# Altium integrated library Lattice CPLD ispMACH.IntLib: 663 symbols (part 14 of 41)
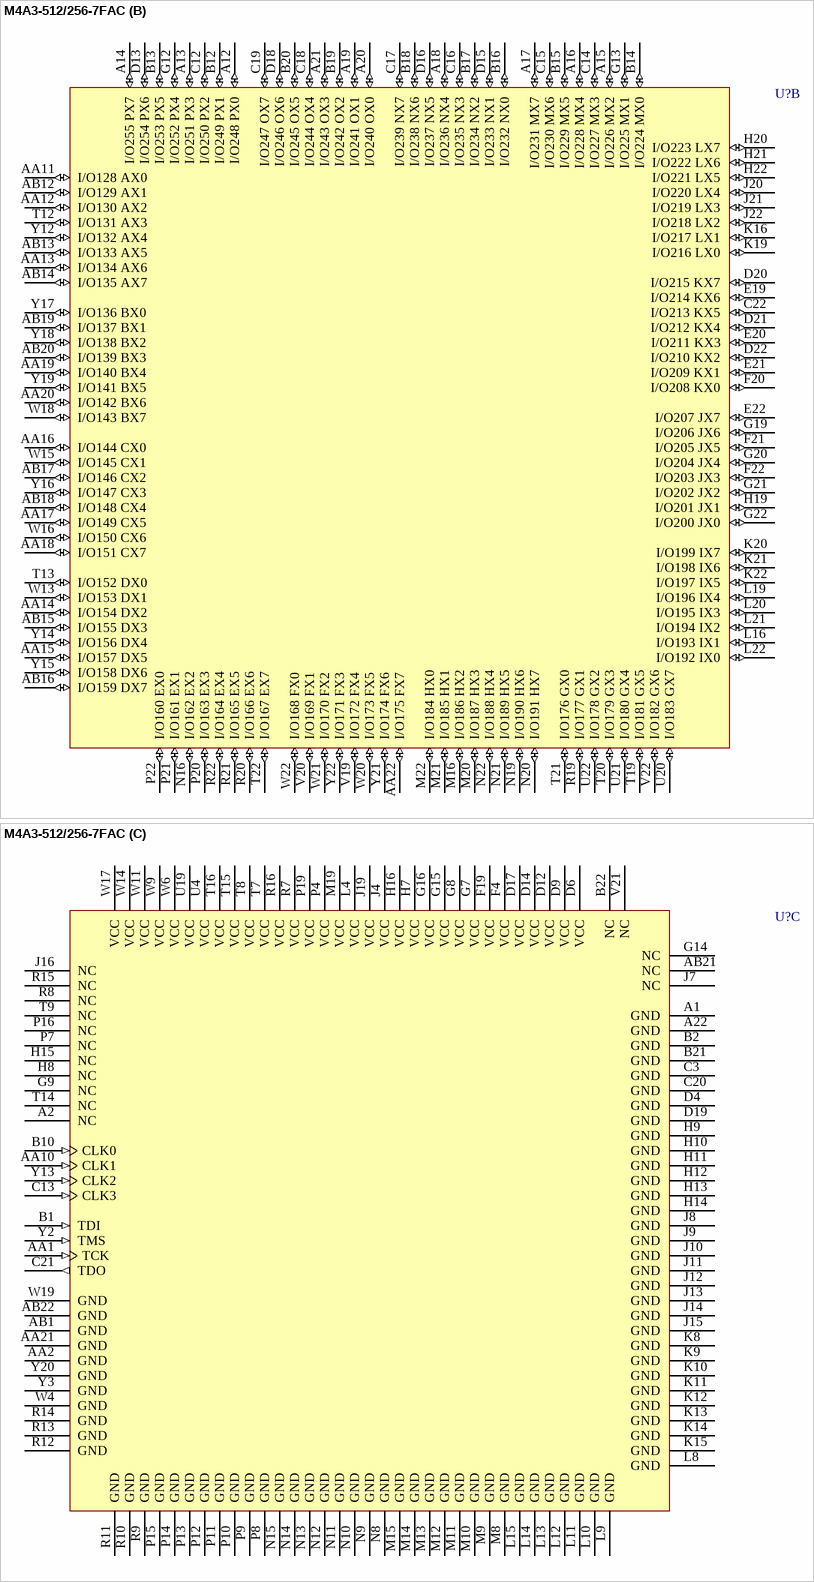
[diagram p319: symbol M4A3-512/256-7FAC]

## M4A3-512/256-7FAC
designator U?
High-Performance EE CMOS In-System Programmable Logic
footprint fpBGA388 (BGA, 388-Leads, Body 23x23mm, Pitch 1mm)
3D model M4A3-fpBGA388 (388-Ball Fine Pitch Ball Grid Array (fpBGA388))
part A pins: A3 I/O10 B2 (io), A4 I/O8 B0 (io), A5 I/O22 C6 (io), A6 I/O17 C1 (io), A7 I/O30 D6 (io), A8 I/O27 D3 (io), A9 I/O6 A6 (io), A10 I/O5 A5 (io), A11 I/O0 A0 (io), AA3 I/O116 O4 (io), AA4 I/O113 O1 (io), AA5 I/O109 N5 (io), AA6 I/O108 N4 (io), AA7 I/O103 M7 (io), AA8 I/O100 M4 (io), AA9 I/O127 P7 (io), AB2 I/O117 O5 (io), AB3 I/O114 O2 (io), AB4 I/O112 O0 (io), AB5 I/O107 N3 (io), AB6 I/O105 N1 (io), AB7 I/O102 M6 (io), AB8 I/O97 M1 (io), AB9 I/O126 P6 (io), AB10 I/O124 P4 (io), AB11 I/O120 P0 (io), B3 I/O13 B5 (io), B4 I/O12 B4 (io), B5 I/O9 B1 (io), B6 I/O20 C4 (io), B7 I/O31 D7 (io), B8 I/O29 D5 (io), B9 I/O26 D2 (io), B11 I/O2 A2 (io), C1 I/O44 F4 (io), C2 I/O47 F7 (io), C4 I/O15 B7 (io), C5 I/O11 B3 (io), C6 I/O23 C7 (io), C7 I/O18 C2 (io), C8 I/O16 C0 (io), C9 I/O25 D1 (io), C10 I/O7 A7 (io), C11 I/O11 A1 (io), D1 I/O41 F1 (io), D2 I/O43 F3 (io), D3 I/O46 F6 (io), D5 I/O14 B6 (io), D7 I/O21 C5 (io), D8 I/O19 C3 (io), D10 I/O24 D0 (io), D11 I/O3 A3 (io), E1 I/O54 G6 (io), E2 I/O40 F0 (io), E3 I/O42 F2 (io), E4 I/O45 F5 (io), F1 I/O50 G2 (io), F2 I/O52 G4 (io), F3 I/O55 G7 (io), G1 I/O39 E7 (io), G2 I/O49 G1 (io), G3 I/O51 G3 (io), G4 I/O53 G5 (io), G10 I/O28 D4 (io), G11 I/O4 A4 (io), H1 I/O36 E4 (io), H2 I/O37 E5 (io), H3 I/O38 E6 (io), H4 I/O48 G0 (io), J1 I/O32 E0 (io), J2 I/O34 E2 (io), J3 I/O35 E3 (io), K1 I/O60 H4 (io), K2 I/O61 H5 (io), K3 I/O62 H6 (io), K4 I/O63 H7 (io), K7 I/O33 E1 (io), L1 I/O56 H0 (io), L2 I/O57 H1 (io), L3 I/O59 H3 (io), L7 I/O58 H2 (io), M1 I/O64 I0 (io), M2 I/O66 I2 (io), M3 I/O65 I1 (io), M4 I/O67 I3 (io), M7 I/O69 I5 (io), N1 I/O68 I4 (io), N2 I/O70 I6 (io), N3 I/O71 I7 (io), N4 I/O88 L0 (io), N7 I/O89 L1 (io), P1 I/O90 L2 (io), P2 I/O91 L3 (io), P3 I/O92 L4 (io), R1 I/O93 L5 (io), R2 I/O94 L6 (io), R3 I/O95 L7 (io), R4 I/O74 J2 (io), T1 I/O72 J0 (io), T2 I/O73 J1 (io), T3 I/O76 J4 (io), T4 I/O78 J6 (io), T10 I/O98 M2 (io), T11 I/O122 P2 (io), U1 I/O75 J3 (io), U2 I/O77 J5 (io), U3 I/O80 K0 (io), V1 I/O79 J7 (io), V2 I/O81 K1 (io), V3 I/O83 K3 (io), V4 I/O86 K6 (io), W1 I/O82 K2 (io), W2 I/O84 K4 (io), W3 I/O87 K7 (io), W5 I/O119 O7 (io), W7 I/O111 N7 (io), W8 I/O104 N0 (io), W10 I/O96 M0 (io), W12 I/O123 P3 (io), Y1 I/O85 K5 (io), Y4 I/O118 O6 (io), Y5 I/O115 O3 (io), Y6 I/O110 N6 (io), Y7 I/O106 N2 (io), Y8 I/O101 M5 (io), Y9 I/O99 M3 (io), Y10 I/O125 P5 (io), Y11 I/O121 P1 (io)
part B pins: A12 I/O248 PX0 (io), A13 I/O251 PX3 (io), A14 I/O255 PX7 (io), A15 I/O226 MX2 (io), A16 I/O228 MX4 (io), A17 I/O231 MX7 (io), A18 I/O236 NX4 (io), A19 I/O241 OX1 (io), A20 I/O240 OX0 (io), A21 I/O243 OX3 (io), AA11 I/O128 AX0 (io), AA12 I/O130 AX2 (io), AA13 I/O134 AX6 (io), AA14 I/O154 DX2 (io), AA15 I/O157 DX5 (io), AA16 I/O144 CX0 (io), AA17 I/O149 CX5 (io), AA18 I/O151 CX7 (io), AA19 I/O140 BX4 (io), AA20 I/O142 BX6 (io), AA22 I/O175 FX7 (io), AB12 I/O129 AX1 (io), AB13 I/O133 AX5 (io), AB14 I/O135 AX7 (io), AB15 I/O155 DX3 (io), AB16 I/O159 DX7 (io), AB17 I/O146 CX2 (io), AB18 I/O148 CX4 (io), AB19 I/O137 BX1 (io), AB20 I/O139 BX3 (io), B12 I/O249 PX1 (io), B13 I/O253 PX5 (io), B14 I/O224 MX0 (io), B15 I/O229 MX5 (io), B16 I/O232 NX0 (io), B17 I/O234 NX2 (io), B18 I/O238 NX6 (io), B19 I/O242 OX2 (io), B20 I/O245 OX5 (io), C12 I/O250 PX2 (io), C14 I/O227 MX3 (io), C15 I/O230 MX6 (io), C16 I/O235 NX3 (io), C17 I/O239 NX7 (io), C18 I/O244 OX4 (io), C19 I/O247 OX7 (io), C22 I/O213 KX5 (io), D13 I/O254 PX6 (io), D15 I/O233 NX1 (io), D16 I/O237 NX5 (io), D18 I/O246 OX6 (io), D20 I/O215 KX7 (io), D21 I/O212 KX4 (io), D22 I/O210 KX2 (io), E19 I/O214 KX6 (io), E20 I/O211 KX3 (io), E21 I/O209 KX1 (io), E22 I/O207 JX7 (io), F20 I/O208 KX0 (io), F21 I/O205 JX5 (io), F22 I/O203 JX3 (io), G12 I/O252 PX4 (io), G13 I/O225 MX1 (io), G19 I/O206 JX6 (io), G20 I/O204 JX4 (io), G21 I/O202 JX2 (io), G22 I/O200 JX0 (io), H19 I/O201 JX1 (io), H20 I/O223 LX7 (io), H21 I/O222 LX6 (io), H22 I/O221 LX5 (io), J20 I/O220 LX4 (io), J21 I/O219 LX3 (io), J22 I/O218 LX2 (io), K16 I/O217 LX1 (io), K19 I/O216 LX0 (io), K20 I/O199 IX7 (io), K21 I/O198 IX6 (io), K22 I/O197 IX5 (io), L16 I/O193 IX1 (io), L19 I/O196 IX4 (io), L20 I/O195 IX3 (io), L21 I/O194 IX2 (io), L22 I/O192 IX0 (io), M16 I/O186 HX2 (io), M20 I/O187 HX3 (io), M21 I/O185 HX1 (io), M22 I/O184 HX0 (io), N16 I/O162 EX2 (io), N19 I/O190 HX6 (io), N20 I/O191 HX7 (io), N21 I/O189 HX5 (io), N22 I/O188 HX4 (io), P20 I/O163 EX3 (io), P21 I/O161 EX1 (io), P22 I/O160 EX0 (io), R19 I/O177 GX1 (io), R20 I/O166 EX6 (io), R21 I/O165 EX5 (io), R22 I/O164 EX4 (io), T12 I/O131 AX3 (io), T13 I/O152 DX0 (io), T19 I/O181 GX5 (io), T20 I/O179 GX3 (io), T21 I/O176 GX0 (io), T22 I/O167 EX7 (io), U20 I/O183 GX7 (io), U21 I/O180 GX4 (io), U22 I/O178 GX2 (io), V19 I/O172 FX4 (io), V20 I/O169 FX1 (io), V22 I/O182 GX6 (io), W13 I/O153 DX1 (io), W15 I/O145 CX1 (io), W16 I/O150 CX6 (io), W18 I/O143 BX7 (io), W20 I/O173 FX5 (io), W21 I/O170 FX2 (io), W22 I/O168 FX0 (io), Y12 I/O132 AX4 (io), Y14 I/O156 DX4 (io), Y15 I/O158 DX6 (io), Y16 I/O147 CX3 (io), Y17 I/O136 BX0 (io), Y18 I/O138 BX2 (io), Y19 I/O141 BX5 (io), Y21 I/O174 FX6 (io), Y22 I/O171 FX3 (io)
part C pins: A1 GND (power), A2 NC, A22 GND (power), AA1 TCK (in), AA2 GND (power), AA10 CLK1 (in), AA21 GND (power), AB1 GND (power), AB21 NC, AB22 GND (power), B1 TDI (in), B2 GND (power), B10 CLK0 (in), B21 GND (power), B22 NC, C3 GND (power), C13 CLK3 (in), C20 GND (power), C21 TDO (out), D4 GND (power), D6 VCC (power), D9 VCC (power), D12 VCC (power), D14 VCC (power), D17 VCC (power), D19 GND (power), F4 VCC (power), F19 VCC (power), G7 VCC (power), G8 VCC (power), G9 NC, G14 NC, G15 VCC (power), G16 VCC (power), H7 VCC (power), H8 NC, H9 GND (power), H10 GND (power), H11 GND (power), H12 GND (power), H13 GND (power), H14 GND (power), H15 NC, H16 VCC (power), J4 VCC (power), J7 NC, J8 GND (power), J9 GND (power), J10 GND (power), J11 GND (power), J12 GND (power), J13 GND (power), J14 GND (power), J15 GND (power), J16 NC, J19 VCC (power), K8 GND (power), K9 GND (power), K10 GND (power), K11 GND (power), K12 GND (power), K13 GND (power), K14 GND (power), K15 GND (power), L4 VCC (power), L8 GND (power), L9 GND (power), L10 GND (power), L11 GND (power), L12 GND (power), L13 GND (power), L14 GND (power), L15 GND (power), M8 GND (power), M9 GND (power), M10 GND (power), M11 GND (power), M12 GND (power), M13 GND (power), M14 GND (power), M15 GND (power), M19 VCC (power), N8 GND (power), N9 GND (power), N10 GND (power), N11 GND (power), N12 GND (power), N13 GND (power), N14 GND (power), N15 GND (power), P4 VCC (power), P7 NC, P8 GND (power), P9 GND (power), P10 GND (power), P11 GND (power), P12 GND (power), P13 GND (power), P14 GND (power), P15 GND (power), P16 NC, P19 VCC (power), R7 VCC (power), R8 NC, R9 GND (power), R10 GND (power), R11 GND (power), R12 GND (power), R13 GND (power), R14 GND (power), R15 NC, R16 VCC (power), T7 VCC (power), T8 VCC (power), T9 NC, T14 NC, T15 VCC (power), T16 VCC (power), U4 VCC (power), U19 VCC (power), V21 NC, W4 GND (power), W6 VCC (power), W9 VCC (power), W11 VCC (power), W14 VCC (power), W17 VCC (power), W19 GND (power), Y2 TMS (in), Y3 GND (power), Y13 CLK2 (in), Y20 GND (power)

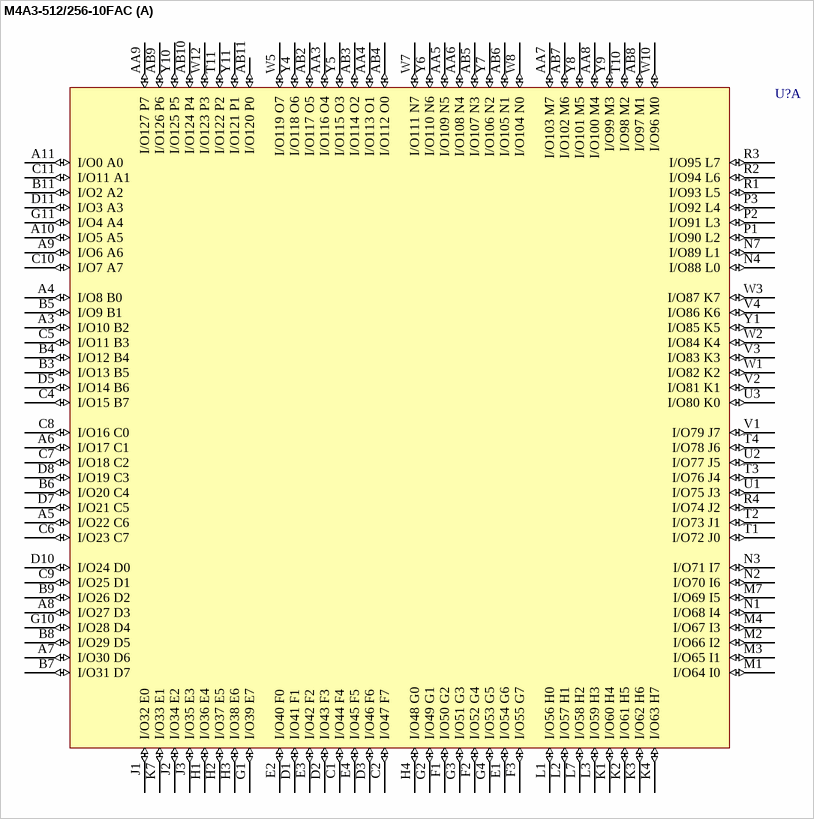
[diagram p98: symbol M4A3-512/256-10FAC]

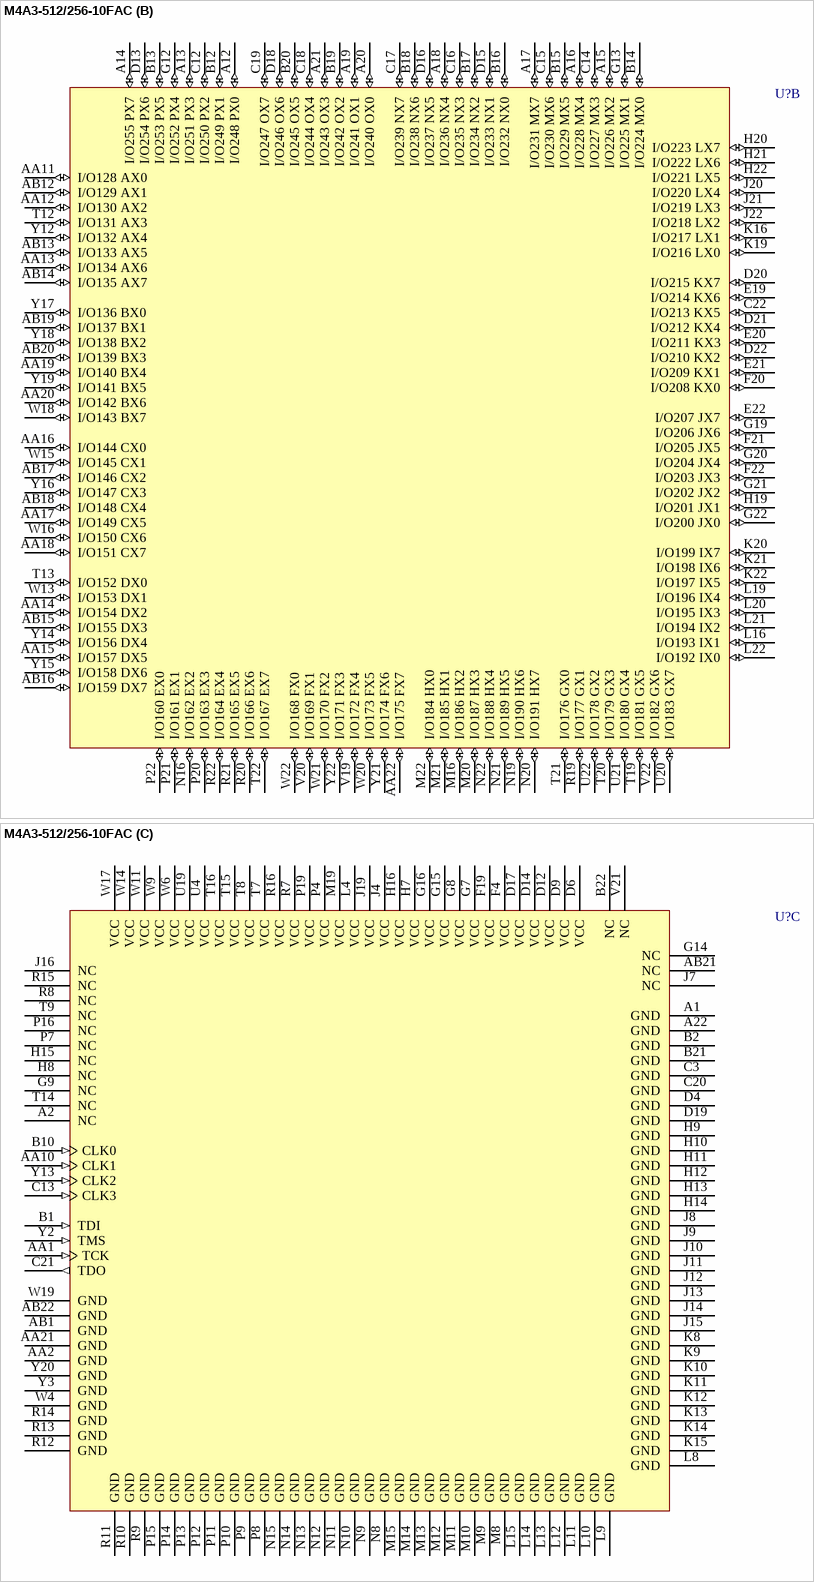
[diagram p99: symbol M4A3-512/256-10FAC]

## M4A3-512/256-10FAC
designator U?
High-Performance EE CMOS In-System Programmable Logic
footprint fpBGA388 (BGA, 388-Leads, Body 23x23mm, Pitch 1mm)
3D model M4A3-fpBGA388 (388-Ball Fine Pitch Ball Grid Array (fpBGA388))
part A pins: A3 I/O10 B2 (io), A4 I/O8 B0 (io), A5 I/O22 C6 (io), A6 I/O17 C1 (io), A7 I/O30 D6 (io), A8 I/O27 D3 (io), A9 I/O6 A6 (io), A10 I/O5 A5 (io), A11 I/O0 A0 (io), AA3 I/O116 O4 (io), AA4 I/O113 O1 (io), AA5 I/O109 N5 (io), AA6 I/O108 N4 (io), AA7 I/O103 M7 (io), AA8 I/O100 M4 (io), AA9 I/O127 P7 (io), AB2 I/O117 O5 (io), AB3 I/O114 O2 (io), AB4 I/O112 O0 (io), AB5 I/O107 N3 (io), AB6 I/O105 N1 (io), AB7 I/O102 M6 (io), AB8 I/O97 M1 (io), AB9 I/O126 P6 (io), AB10 I/O124 P4 (io), AB11 I/O120 P0 (io), B3 I/O13 B5 (io), B4 I/O12 B4 (io), B5 I/O9 B1 (io), B6 I/O20 C4 (io), B7 I/O31 D7 (io), B8 I/O29 D5 (io), B9 I/O26 D2 (io), B11 I/O2 A2 (io), C1 I/O44 F4 (io), C2 I/O47 F7 (io), C4 I/O15 B7 (io), C5 I/O11 B3 (io), C6 I/O23 C7 (io), C7 I/O18 C2 (io), C8 I/O16 C0 (io), C9 I/O25 D1 (io), C10 I/O7 A7 (io), C11 I/O11 A1 (io), D1 I/O41 F1 (io), D2 I/O43 F3 (io), D3 I/O46 F6 (io), D5 I/O14 B6 (io), D7 I/O21 C5 (io), D8 I/O19 C3 (io), D10 I/O24 D0 (io), D11 I/O3 A3 (io), E1 I/O54 G6 (io), E2 I/O40 F0 (io), E3 I/O42 F2 (io), E4 I/O45 F5 (io), F1 I/O50 G2 (io), F2 I/O52 G4 (io), F3 I/O55 G7 (io), G1 I/O39 E7 (io), G2 I/O49 G1 (io), G3 I/O51 G3 (io), G4 I/O53 G5 (io), G10 I/O28 D4 (io), G11 I/O4 A4 (io), H1 I/O36 E4 (io), H2 I/O37 E5 (io), H3 I/O38 E6 (io), H4 I/O48 G0 (io), J1 I/O32 E0 (io), J2 I/O34 E2 (io), J3 I/O35 E3 (io), K1 I/O60 H4 (io), K2 I/O61 H5 (io), K3 I/O62 H6 (io), K4 I/O63 H7 (io), K7 I/O33 E1 (io), L1 I/O56 H0 (io), L2 I/O57 H1 (io), L3 I/O59 H3 (io), L7 I/O58 H2 (io), M1 I/O64 I0 (io), M2 I/O66 I2 (io), M3 I/O65 I1 (io), M4 I/O67 I3 (io), M7 I/O69 I5 (io), N1 I/O68 I4 (io), N2 I/O70 I6 (io), N3 I/O71 I7 (io), N4 I/O88 L0 (io), N7 I/O89 L1 (io), P1 I/O90 L2 (io), P2 I/O91 L3 (io), P3 I/O92 L4 (io), R1 I/O93 L5 (io), R2 I/O94 L6 (io), R3 I/O95 L7 (io), R4 I/O74 J2 (io), T1 I/O72 J0 (io), T2 I/O73 J1 (io), T3 I/O76 J4 (io), T4 I/O78 J6 (io), T10 I/O98 M2 (io), T11 I/O122 P2 (io), U1 I/O75 J3 (io), U2 I/O77 J5 (io), U3 I/O80 K0 (io), V1 I/O79 J7 (io), V2 I/O81 K1 (io), V3 I/O83 K3 (io), V4 I/O86 K6 (io), W1 I/O82 K2 (io), W2 I/O84 K4 (io), W3 I/O87 K7 (io), W5 I/O119 O7 (io), W7 I/O111 N7 (io), W8 I/O104 N0 (io), W10 I/O96 M0 (io), W12 I/O123 P3 (io), Y1 I/O85 K5 (io), Y4 I/O118 O6 (io), Y5 I/O115 O3 (io), Y6 I/O110 N6 (io), Y7 I/O106 N2 (io), Y8 I/O101 M5 (io), Y9 I/O99 M3 (io), Y10 I/O125 P5 (io), Y11 I/O121 P1 (io)
part B pins: A12 I/O248 PX0 (io), A13 I/O251 PX3 (io), A14 I/O255 PX7 (io), A15 I/O226 MX2 (io), A16 I/O228 MX4 (io), A17 I/O231 MX7 (io), A18 I/O236 NX4 (io), A19 I/O241 OX1 (io), A20 I/O240 OX0 (io), A21 I/O243 OX3 (io), AA11 I/O128 AX0 (io), AA12 I/O130 AX2 (io), AA13 I/O134 AX6 (io), AA14 I/O154 DX2 (io), AA15 I/O157 DX5 (io), AA16 I/O144 CX0 (io), AA17 I/O149 CX5 (io), AA18 I/O151 CX7 (io), AA19 I/O140 BX4 (io), AA20 I/O142 BX6 (io), AA22 I/O175 FX7 (io), AB12 I/O129 AX1 (io), AB13 I/O133 AX5 (io), AB14 I/O135 AX7 (io), AB15 I/O155 DX3 (io), AB16 I/O159 DX7 (io), AB17 I/O146 CX2 (io), AB18 I/O148 CX4 (io), AB19 I/O137 BX1 (io), AB20 I/O139 BX3 (io), B12 I/O249 PX1 (io), B13 I/O253 PX5 (io), B14 I/O224 MX0 (io), B15 I/O229 MX5 (io), B16 I/O232 NX0 (io), B17 I/O234 NX2 (io), B18 I/O238 NX6 (io), B19 I/O242 OX2 (io), B20 I/O245 OX5 (io), C12 I/O250 PX2 (io), C14 I/O227 MX3 (io), C15 I/O230 MX6 (io), C16 I/O235 NX3 (io), C17 I/O239 NX7 (io), C18 I/O244 OX4 (io), C19 I/O247 OX7 (io), C22 I/O213 KX5 (io), D13 I/O254 PX6 (io), D15 I/O233 NX1 (io), D16 I/O237 NX5 (io), D18 I/O246 OX6 (io), D20 I/O215 KX7 (io), D21 I/O212 KX4 (io), D22 I/O210 KX2 (io), E19 I/O214 KX6 (io), E20 I/O211 KX3 (io), E21 I/O209 KX1 (io), E22 I/O207 JX7 (io), F20 I/O208 KX0 (io), F21 I/O205 JX5 (io), F22 I/O203 JX3 (io), G12 I/O252 PX4 (io), G13 I/O225 MX1 (io), G19 I/O206 JX6 (io), G20 I/O204 JX4 (io), G21 I/O202 JX2 (io), G22 I/O200 JX0 (io), H19 I/O201 JX1 (io), H20 I/O223 LX7 (io), H21 I/O222 LX6 (io), H22 I/O221 LX5 (io), J20 I/O220 LX4 (io), J21 I/O219 LX3 (io), J22 I/O218 LX2 (io), K16 I/O217 LX1 (io), K19 I/O216 LX0 (io), K20 I/O199 IX7 (io), K21 I/O198 IX6 (io), K22 I/O197 IX5 (io), L16 I/O193 IX1 (io), L19 I/O196 IX4 (io), L20 I/O195 IX3 (io), L21 I/O194 IX2 (io), L22 I/O192 IX0 (io), M16 I/O186 HX2 (io), M20 I/O187 HX3 (io), M21 I/O185 HX1 (io), M22 I/O184 HX0 (io), N16 I/O162 EX2 (io), N19 I/O190 HX6 (io), N20 I/O191 HX7 (io), N21 I/O189 HX5 (io), N22 I/O188 HX4 (io), P20 I/O163 EX3 (io), P21 I/O161 EX1 (io), P22 I/O160 EX0 (io), R19 I/O177 GX1 (io), R20 I/O166 EX6 (io), R21 I/O165 EX5 (io), R22 I/O164 EX4 (io), T12 I/O131 AX3 (io), T13 I/O152 DX0 (io), T19 I/O181 GX5 (io), T20 I/O179 GX3 (io), T21 I/O176 GX0 (io), T22 I/O167 EX7 (io), U20 I/O183 GX7 (io), U21 I/O180 GX4 (io), U22 I/O178 GX2 (io), V19 I/O172 FX4 (io), V20 I/O169 FX1 (io), V22 I/O182 GX6 (io), W13 I/O153 DX1 (io), W15 I/O145 CX1 (io), W16 I/O150 CX6 (io), W18 I/O143 BX7 (io), W20 I/O173 FX5 (io), W21 I/O170 FX2 (io), W22 I/O168 FX0 (io), Y12 I/O132 AX4 (io), Y14 I/O156 DX4 (io), Y15 I/O158 DX6 (io), Y16 I/O147 CX3 (io), Y17 I/O136 BX0 (io), Y18 I/O138 BX2 (io), Y19 I/O141 BX5 (io), Y21 I/O174 FX6 (io), Y22 I/O171 FX3 (io)
part C pins: A1 GND (power), A2 NC, A22 GND (power), AA1 TCK (in), AA2 GND (power), AA10 CLK1 (in), AA21 GND (power), AB1 GND (power), AB21 NC, AB22 GND (power), B1 TDI (in), B2 GND (power), B10 CLK0 (in), B21 GND (power), B22 NC, C3 GND (power), C13 CLK3 (in), C20 GND (power), C21 TDO (out), D4 GND (power), D6 VCC (power), D9 VCC (power), D12 VCC (power), D14 VCC (power), D17 VCC (power), D19 GND (power), F4 VCC (power), F19 VCC (power), G7 VCC (power), G8 VCC (power), G9 NC, G14 NC, G15 VCC (power), G16 VCC (power), H7 VCC (power), H8 NC, H9 GND (power), H10 GND (power), H11 GND (power), H12 GND (power), H13 GND (power), H14 GND (power), H15 NC, H16 VCC (power), J4 VCC (power), J7 NC, J8 GND (power), J9 GND (power), J10 GND (power), J11 GND (power), J12 GND (power), J13 GND (power), J14 GND (power), J15 GND (power), J16 NC, J19 VCC (power), K8 GND (power), K9 GND (power), K10 GND (power), K11 GND (power), K12 GND (power), K13 GND (power), K14 GND (power), K15 GND (power), L4 VCC (power), L8 GND (power), L9 GND (power), L10 GND (power), L11 GND (power), L12 GND (power), L13 GND (power), L14 GND (power), L15 GND (power), M8 GND (power), M9 GND (power), M10 GND (power), M11 GND (power), M12 GND (power), M13 GND (power), M14 GND (power), M15 GND (power), M19 VCC (power), N8 GND (power), N9 GND (power), N10 GND (power), N11 GND (power), N12 GND (power), N13 GND (power), N14 GND (power), N15 GND (power), P4 VCC (power), P7 NC, P8 GND (power), P9 GND (power), P10 GND (power), P11 GND (power), P12 GND (power), P13 GND (power), P14 GND (power), P15 GND (power), P16 NC, P19 VCC (power), R7 VCC (power), R8 NC, R9 GND (power), R10 GND (power), R11 GND (power), R12 GND (power), R13 GND (power), R14 GND (power), R15 NC, R16 VCC (power), T7 VCC (power), T8 VCC (power), T9 NC, T14 NC, T15 VCC (power), T16 VCC (power), U4 VCC (power), U19 VCC (power), V21 NC, W4 GND (power), W6 VCC (power), W9 VCC (power), W11 VCC (power), W14 VCC (power), W17 VCC (power), W19 GND (power), Y2 TMS (in), Y3 GND (power), Y13 CLK2 (in), Y20 GND (power)

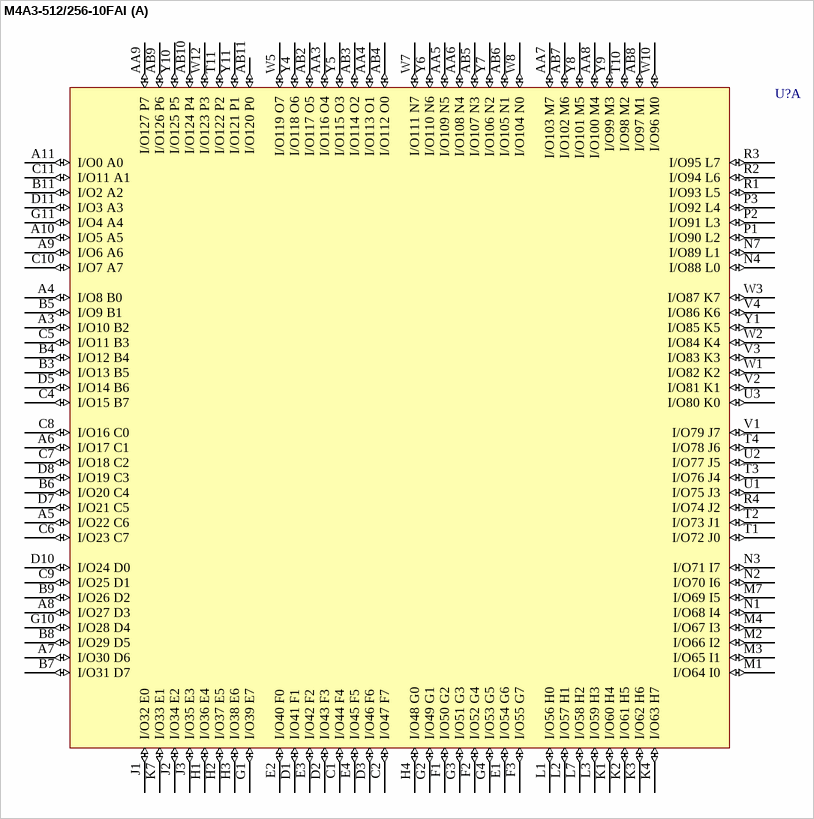
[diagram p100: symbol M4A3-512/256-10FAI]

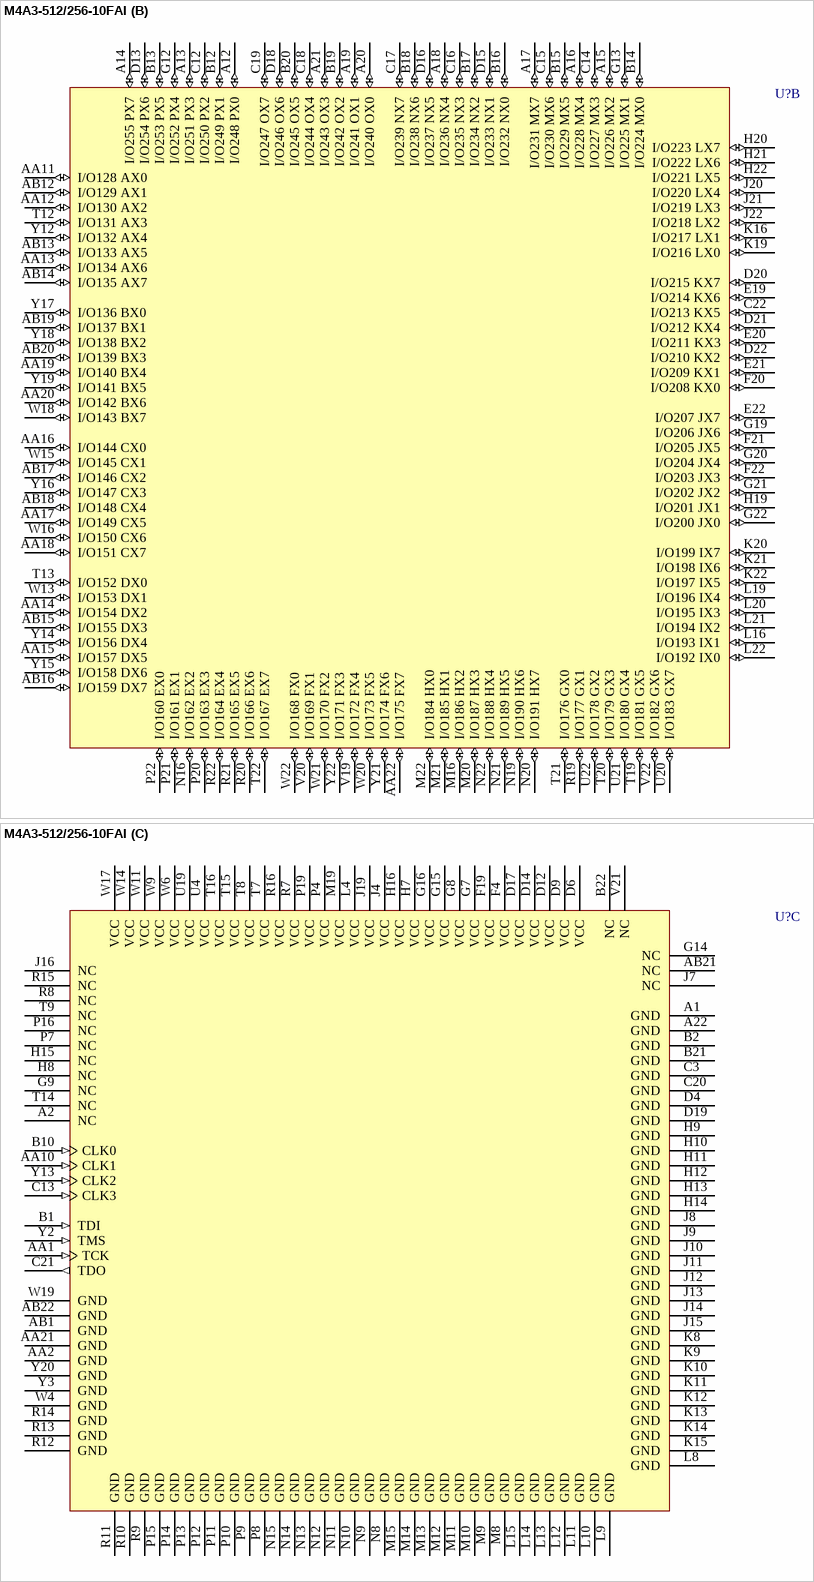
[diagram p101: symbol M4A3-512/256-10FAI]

## M4A3-512/256-10FAI
designator U?
High-Performance EE CMOS In-System Programmable Logic
footprint fpBGA388 (BGA, 388-Leads, Body 23x23mm, Pitch 1mm)
3D model M4A3-fpBGA388 (388-Ball Fine Pitch Ball Grid Array (fpBGA388))
part A pins: A3 I/O10 B2 (io), A4 I/O8 B0 (io), A5 I/O22 C6 (io), A6 I/O17 C1 (io), A7 I/O30 D6 (io), A8 I/O27 D3 (io), A9 I/O6 A6 (io), A10 I/O5 A5 (io), A11 I/O0 A0 (io), AA3 I/O116 O4 (io), AA4 I/O113 O1 (io), AA5 I/O109 N5 (io), AA6 I/O108 N4 (io), AA7 I/O103 M7 (io), AA8 I/O100 M4 (io), AA9 I/O127 P7 (io), AB2 I/O117 O5 (io), AB3 I/O114 O2 (io), AB4 I/O112 O0 (io), AB5 I/O107 N3 (io), AB6 I/O105 N1 (io), AB7 I/O102 M6 (io), AB8 I/O97 M1 (io), AB9 I/O126 P6 (io), AB10 I/O124 P4 (io), AB11 I/O120 P0 (io), B3 I/O13 B5 (io), B4 I/O12 B4 (io), B5 I/O9 B1 (io), B6 I/O20 C4 (io), B7 I/O31 D7 (io), B8 I/O29 D5 (io), B9 I/O26 D2 (io), B11 I/O2 A2 (io), C1 I/O44 F4 (io), C2 I/O47 F7 (io), C4 I/O15 B7 (io), C5 I/O11 B3 (io), C6 I/O23 C7 (io), C7 I/O18 C2 (io), C8 I/O16 C0 (io), C9 I/O25 D1 (io), C10 I/O7 A7 (io), C11 I/O11 A1 (io), D1 I/O41 F1 (io), D2 I/O43 F3 (io), D3 I/O46 F6 (io), D5 I/O14 B6 (io), D7 I/O21 C5 (io), D8 I/O19 C3 (io), D10 I/O24 D0 (io), D11 I/O3 A3 (io), E1 I/O54 G6 (io), E2 I/O40 F0 (io), E3 I/O42 F2 (io), E4 I/O45 F5 (io), F1 I/O50 G2 (io), F2 I/O52 G4 (io), F3 I/O55 G7 (io), G1 I/O39 E7 (io), G2 I/O49 G1 (io), G3 I/O51 G3 (io), G4 I/O53 G5 (io), G10 I/O28 D4 (io), G11 I/O4 A4 (io), H1 I/O36 E4 (io), H2 I/O37 E5 (io), H3 I/O38 E6 (io), H4 I/O48 G0 (io), J1 I/O32 E0 (io), J2 I/O34 E2 (io), J3 I/O35 E3 (io), K1 I/O60 H4 (io), K2 I/O61 H5 (io), K3 I/O62 H6 (io), K4 I/O63 H7 (io), K7 I/O33 E1 (io), L1 I/O56 H0 (io), L2 I/O57 H1 (io), L3 I/O59 H3 (io), L7 I/O58 H2 (io), M1 I/O64 I0 (io), M2 I/O66 I2 (io), M3 I/O65 I1 (io), M4 I/O67 I3 (io), M7 I/O69 I5 (io), N1 I/O68 I4 (io), N2 I/O70 I6 (io), N3 I/O71 I7 (io), N4 I/O88 L0 (io), N7 I/O89 L1 (io), P1 I/O90 L2 (io), P2 I/O91 L3 (io), P3 I/O92 L4 (io), R1 I/O93 L5 (io), R2 I/O94 L6 (io), R3 I/O95 L7 (io), R4 I/O74 J2 (io), T1 I/O72 J0 (io), T2 I/O73 J1 (io), T3 I/O76 J4 (io), T4 I/O78 J6 (io), T10 I/O98 M2 (io), T11 I/O122 P2 (io), U1 I/O75 J3 (io), U2 I/O77 J5 (io), U3 I/O80 K0 (io), V1 I/O79 J7 (io), V2 I/O81 K1 (io), V3 I/O83 K3 (io), V4 I/O86 K6 (io), W1 I/O82 K2 (io), W2 I/O84 K4 (io), W3 I/O87 K7 (io), W5 I/O119 O7 (io), W7 I/O111 N7 (io), W8 I/O104 N0 (io), W10 I/O96 M0 (io), W12 I/O123 P3 (io), Y1 I/O85 K5 (io), Y4 I/O118 O6 (io), Y5 I/O115 O3 (io), Y6 I/O110 N6 (io), Y7 I/O106 N2 (io), Y8 I/O101 M5 (io), Y9 I/O99 M3 (io), Y10 I/O125 P5 (io), Y11 I/O121 P1 (io)
part B pins: A12 I/O248 PX0 (io), A13 I/O251 PX3 (io), A14 I/O255 PX7 (io), A15 I/O226 MX2 (io), A16 I/O228 MX4 (io), A17 I/O231 MX7 (io), A18 I/O236 NX4 (io), A19 I/O241 OX1 (io), A20 I/O240 OX0 (io), A21 I/O243 OX3 (io), AA11 I/O128 AX0 (io), AA12 I/O130 AX2 (io), AA13 I/O134 AX6 (io), AA14 I/O154 DX2 (io), AA15 I/O157 DX5 (io), AA16 I/O144 CX0 (io), AA17 I/O149 CX5 (io), AA18 I/O151 CX7 (io), AA19 I/O140 BX4 (io), AA20 I/O142 BX6 (io), AA22 I/O175 FX7 (io), AB12 I/O129 AX1 (io), AB13 I/O133 AX5 (io), AB14 I/O135 AX7 (io), AB15 I/O155 DX3 (io), AB16 I/O159 DX7 (io), AB17 I/O146 CX2 (io), AB18 I/O148 CX4 (io), AB19 I/O137 BX1 (io), AB20 I/O139 BX3 (io), B12 I/O249 PX1 (io), B13 I/O253 PX5 (io), B14 I/O224 MX0 (io), B15 I/O229 MX5 (io), B16 I/O232 NX0 (io), B17 I/O234 NX2 (io), B18 I/O238 NX6 (io), B19 I/O242 OX2 (io), B20 I/O245 OX5 (io), C12 I/O250 PX2 (io), C14 I/O227 MX3 (io), C15 I/O230 MX6 (io), C16 I/O235 NX3 (io), C17 I/O239 NX7 (io), C18 I/O244 OX4 (io), C19 I/O247 OX7 (io), C22 I/O213 KX5 (io), D13 I/O254 PX6 (io), D15 I/O233 NX1 (io), D16 I/O237 NX5 (io), D18 I/O246 OX6 (io), D20 I/O215 KX7 (io), D21 I/O212 KX4 (io), D22 I/O210 KX2 (io), E19 I/O214 KX6 (io), E20 I/O211 KX3 (io), E21 I/O209 KX1 (io), E22 I/O207 JX7 (io), F20 I/O208 KX0 (io), F21 I/O205 JX5 (io), F22 I/O203 JX3 (io), G12 I/O252 PX4 (io), G13 I/O225 MX1 (io), G19 I/O206 JX6 (io), G20 I/O204 JX4 (io), G21 I/O202 JX2 (io), G22 I/O200 JX0 (io), H19 I/O201 JX1 (io), H20 I/O223 LX7 (io), H21 I/O222 LX6 (io), H22 I/O221 LX5 (io), J20 I/O220 LX4 (io), J21 I/O219 LX3 (io), J22 I/O218 LX2 (io), K16 I/O217 LX1 (io), K19 I/O216 LX0 (io), K20 I/O199 IX7 (io), K21 I/O198 IX6 (io), K22 I/O197 IX5 (io), L16 I/O193 IX1 (io), L19 I/O196 IX4 (io), L20 I/O195 IX3 (io), L21 I/O194 IX2 (io), L22 I/O192 IX0 (io), M16 I/O186 HX2 (io), M20 I/O187 HX3 (io), M21 I/O185 HX1 (io), M22 I/O184 HX0 (io), N16 I/O162 EX2 (io), N19 I/O190 HX6 (io), N20 I/O191 HX7 (io), N21 I/O189 HX5 (io), N22 I/O188 HX4 (io), P20 I/O163 EX3 (io), P21 I/O161 EX1 (io), P22 I/O160 EX0 (io), R19 I/O177 GX1 (io), R20 I/O166 EX6 (io), R21 I/O165 EX5 (io), R22 I/O164 EX4 (io), T12 I/O131 AX3 (io), T13 I/O152 DX0 (io), T19 I/O181 GX5 (io), T20 I/O179 GX3 (io), T21 I/O176 GX0 (io), T22 I/O167 EX7 (io), U20 I/O183 GX7 (io), U21 I/O180 GX4 (io), U22 I/O178 GX2 (io), V19 I/O172 FX4 (io), V20 I/O169 FX1 (io), V22 I/O182 GX6 (io), W13 I/O153 DX1 (io), W15 I/O145 CX1 (io), W16 I/O150 CX6 (io), W18 I/O143 BX7 (io), W20 I/O173 FX5 (io), W21 I/O170 FX2 (io), W22 I/O168 FX0 (io), Y12 I/O132 AX4 (io), Y14 I/O156 DX4 (io), Y15 I/O158 DX6 (io), Y16 I/O147 CX3 (io), Y17 I/O136 BX0 (io), Y18 I/O138 BX2 (io), Y19 I/O141 BX5 (io), Y21 I/O174 FX6 (io), Y22 I/O171 FX3 (io)
part C pins: A1 GND (power), A2 NC, A22 GND (power), AA1 TCK (in), AA2 GND (power), AA10 CLK1 (in), AA21 GND (power), AB1 GND (power), AB21 NC, AB22 GND (power), B1 TDI (in), B2 GND (power), B10 CLK0 (in), B21 GND (power), B22 NC, C3 GND (power), C13 CLK3 (in), C20 GND (power), C21 TDO (out), D4 GND (power), D6 VCC (power), D9 VCC (power), D12 VCC (power), D14 VCC (power), D17 VCC (power), D19 GND (power), F4 VCC (power), F19 VCC (power), G7 VCC (power), G8 VCC (power), G9 NC, G14 NC, G15 VCC (power), G16 VCC (power), H7 VCC (power), H8 NC, H9 GND (power), H10 GND (power), H11 GND (power), H12 GND (power), H13 GND (power), H14 GND (power), H15 NC, H16 VCC (power), J4 VCC (power), J7 NC, J8 GND (power), J9 GND (power), J10 GND (power), J11 GND (power), J12 GND (power), J13 GND (power), J14 GND (power), J15 GND (power), J16 NC, J19 VCC (power), K8 GND (power), K9 GND (power), K10 GND (power), K11 GND (power), K12 GND (power), K13 GND (power), K14 GND (power), K15 GND (power), L4 VCC (power), L8 GND (power), L9 GND (power), L10 GND (power), L11 GND (power), L12 GND (power), L13 GND (power), L14 GND (power), L15 GND (power), M8 GND (power), M9 GND (power), M10 GND (power), M11 GND (power), M12 GND (power), M13 GND (power), M14 GND (power), M15 GND (power), M19 VCC (power), N8 GND (power), N9 GND (power), N10 GND (power), N11 GND (power), N12 GND (power), N13 GND (power), N14 GND (power), N15 GND (power), P4 VCC (power), P7 NC, P8 GND (power), P9 GND (power), P10 GND (power), P11 GND (power), P12 GND (power), P13 GND (power), P14 GND (power), P15 GND (power), P16 NC, P19 VCC (power), R7 VCC (power), R8 NC, R9 GND (power), R10 GND (power), R11 GND (power), R12 GND (power), R13 GND (power), R14 GND (power), R15 NC, R16 VCC (power), T7 VCC (power), T8 VCC (power), T9 NC, T14 NC, T15 VCC (power), T16 VCC (power), U4 VCC (power), U19 VCC (power), V21 NC, W4 GND (power), W6 VCC (power), W9 VCC (power), W11 VCC (power), W14 VCC (power), W17 VCC (power), W19 GND (power), Y2 TMS (in), Y3 GND (power), Y13 CLK2 (in), Y20 GND (power)

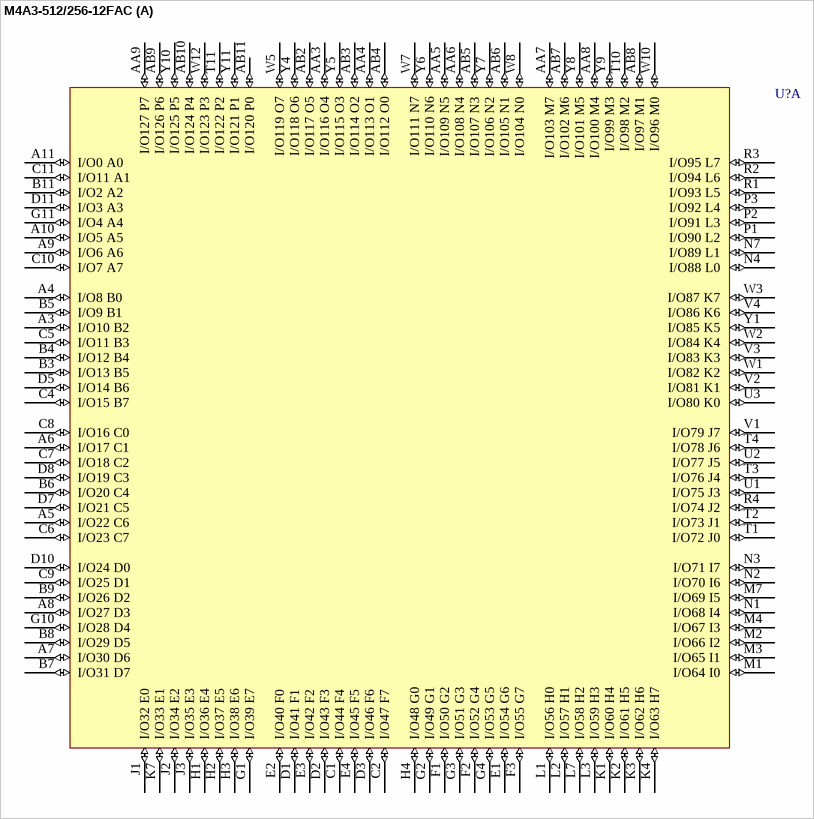
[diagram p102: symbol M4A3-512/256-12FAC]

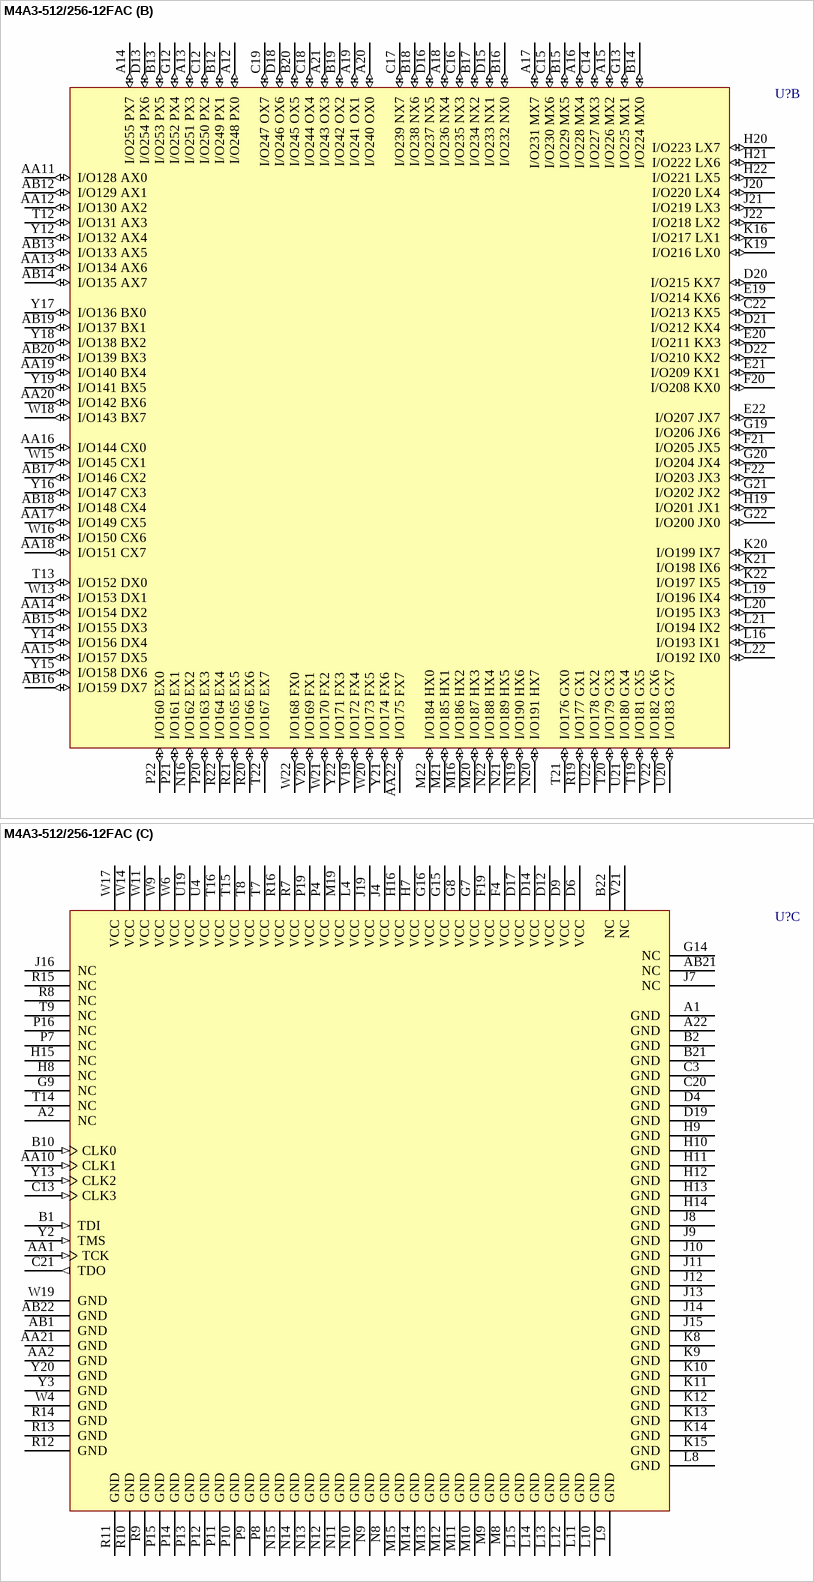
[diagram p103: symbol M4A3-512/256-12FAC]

## M4A3-512/256-12FAC
designator U?
High-Performance EE CMOS In-System Programmable Logic
footprint fpBGA388 (BGA, 388-Leads, Body 23x23mm, Pitch 1mm)
3D model M4A3-fpBGA388 (388-Ball Fine Pitch Ball Grid Array (fpBGA388))
part A pins: A3 I/O10 B2 (io), A4 I/O8 B0 (io), A5 I/O22 C6 (io), A6 I/O17 C1 (io), A7 I/O30 D6 (io), A8 I/O27 D3 (io), A9 I/O6 A6 (io), A10 I/O5 A5 (io), A11 I/O0 A0 (io), AA3 I/O116 O4 (io), AA4 I/O113 O1 (io), AA5 I/O109 N5 (io), AA6 I/O108 N4 (io), AA7 I/O103 M7 (io), AA8 I/O100 M4 (io), AA9 I/O127 P7 (io), AB2 I/O117 O5 (io), AB3 I/O114 O2 (io), AB4 I/O112 O0 (io), AB5 I/O107 N3 (io), AB6 I/O105 N1 (io), AB7 I/O102 M6 (io), AB8 I/O97 M1 (io), AB9 I/O126 P6 (io), AB10 I/O124 P4 (io), AB11 I/O120 P0 (io), B3 I/O13 B5 (io), B4 I/O12 B4 (io), B5 I/O9 B1 (io), B6 I/O20 C4 (io), B7 I/O31 D7 (io), B8 I/O29 D5 (io), B9 I/O26 D2 (io), B11 I/O2 A2 (io), C1 I/O44 F4 (io), C2 I/O47 F7 (io), C4 I/O15 B7 (io), C5 I/O11 B3 (io), C6 I/O23 C7 (io), C7 I/O18 C2 (io), C8 I/O16 C0 (io), C9 I/O25 D1 (io), C10 I/O7 A7 (io), C11 I/O11 A1 (io), D1 I/O41 F1 (io), D2 I/O43 F3 (io), D3 I/O46 F6 (io), D5 I/O14 B6 (io), D7 I/O21 C5 (io), D8 I/O19 C3 (io), D10 I/O24 D0 (io), D11 I/O3 A3 (io), E1 I/O54 G6 (io), E2 I/O40 F0 (io), E3 I/O42 F2 (io), E4 I/O45 F5 (io), F1 I/O50 G2 (io), F2 I/O52 G4 (io), F3 I/O55 G7 (io), G1 I/O39 E7 (io), G2 I/O49 G1 (io), G3 I/O51 G3 (io), G4 I/O53 G5 (io), G10 I/O28 D4 (io), G11 I/O4 A4 (io), H1 I/O36 E4 (io), H2 I/O37 E5 (io), H3 I/O38 E6 (io), H4 I/O48 G0 (io), J1 I/O32 E0 (io), J2 I/O34 E2 (io), J3 I/O35 E3 (io), K1 I/O60 H4 (io), K2 I/O61 H5 (io), K3 I/O62 H6 (io), K4 I/O63 H7 (io), K7 I/O33 E1 (io), L1 I/O56 H0 (io), L2 I/O57 H1 (io), L3 I/O59 H3 (io), L7 I/O58 H2 (io), M1 I/O64 I0 (io), M2 I/O66 I2 (io), M3 I/O65 I1 (io), M4 I/O67 I3 (io), M7 I/O69 I5 (io), N1 I/O68 I4 (io), N2 I/O70 I6 (io), N3 I/O71 I7 (io), N4 I/O88 L0 (io), N7 I/O89 L1 (io), P1 I/O90 L2 (io), P2 I/O91 L3 (io), P3 I/O92 L4 (io), R1 I/O93 L5 (io), R2 I/O94 L6 (io), R3 I/O95 L7 (io), R4 I/O74 J2 (io), T1 I/O72 J0 (io), T2 I/O73 J1 (io), T3 I/O76 J4 (io), T4 I/O78 J6 (io), T10 I/O98 M2 (io), T11 I/O122 P2 (io), U1 I/O75 J3 (io), U2 I/O77 J5 (io), U3 I/O80 K0 (io), V1 I/O79 J7 (io), V2 I/O81 K1 (io), V3 I/O83 K3 (io), V4 I/O86 K6 (io), W1 I/O82 K2 (io), W2 I/O84 K4 (io), W3 I/O87 K7 (io), W5 I/O119 O7 (io), W7 I/O111 N7 (io), W8 I/O104 N0 (io), W10 I/O96 M0 (io), W12 I/O123 P3 (io), Y1 I/O85 K5 (io), Y4 I/O118 O6 (io), Y5 I/O115 O3 (io), Y6 I/O110 N6 (io), Y7 I/O106 N2 (io), Y8 I/O101 M5 (io), Y9 I/O99 M3 (io), Y10 I/O125 P5 (io), Y11 I/O121 P1 (io)
part B pins: A12 I/O248 PX0 (io), A13 I/O251 PX3 (io), A14 I/O255 PX7 (io), A15 I/O226 MX2 (io), A16 I/O228 MX4 (io), A17 I/O231 MX7 (io), A18 I/O236 NX4 (io), A19 I/O241 OX1 (io), A20 I/O240 OX0 (io), A21 I/O243 OX3 (io), AA11 I/O128 AX0 (io), AA12 I/O130 AX2 (io), AA13 I/O134 AX6 (io), AA14 I/O154 DX2 (io), AA15 I/O157 DX5 (io), AA16 I/O144 CX0 (io), AA17 I/O149 CX5 (io), AA18 I/O151 CX7 (io), AA19 I/O140 BX4 (io), AA20 I/O142 BX6 (io), AA22 I/O175 FX7 (io), AB12 I/O129 AX1 (io), AB13 I/O133 AX5 (io), AB14 I/O135 AX7 (io), AB15 I/O155 DX3 (io), AB16 I/O159 DX7 (io), AB17 I/O146 CX2 (io), AB18 I/O148 CX4 (io), AB19 I/O137 BX1 (io), AB20 I/O139 BX3 (io), B12 I/O249 PX1 (io), B13 I/O253 PX5 (io), B14 I/O224 MX0 (io), B15 I/O229 MX5 (io), B16 I/O232 NX0 (io), B17 I/O234 NX2 (io), B18 I/O238 NX6 (io), B19 I/O242 OX2 (io), B20 I/O245 OX5 (io), C12 I/O250 PX2 (io), C14 I/O227 MX3 (io), C15 I/O230 MX6 (io), C16 I/O235 NX3 (io), C17 I/O239 NX7 (io), C18 I/O244 OX4 (io), C19 I/O247 OX7 (io), C22 I/O213 KX5 (io), D13 I/O254 PX6 (io), D15 I/O233 NX1 (io), D16 I/O237 NX5 (io), D18 I/O246 OX6 (io), D20 I/O215 KX7 (io), D21 I/O212 KX4 (io), D22 I/O210 KX2 (io), E19 I/O214 KX6 (io), E20 I/O211 KX3 (io), E21 I/O209 KX1 (io), E22 I/O207 JX7 (io), F20 I/O208 KX0 (io), F21 I/O205 JX5 (io), F22 I/O203 JX3 (io), G12 I/O252 PX4 (io), G13 I/O225 MX1 (io), G19 I/O206 JX6 (io), G20 I/O204 JX4 (io), G21 I/O202 JX2 (io), G22 I/O200 JX0 (io), H19 I/O201 JX1 (io), H20 I/O223 LX7 (io), H21 I/O222 LX6 (io), H22 I/O221 LX5 (io), J20 I/O220 LX4 (io), J21 I/O219 LX3 (io), J22 I/O218 LX2 (io), K16 I/O217 LX1 (io), K19 I/O216 LX0 (io), K20 I/O199 IX7 (io), K21 I/O198 IX6 (io), K22 I/O197 IX5 (io), L16 I/O193 IX1 (io), L19 I/O196 IX4 (io), L20 I/O195 IX3 (io), L21 I/O194 IX2 (io), L22 I/O192 IX0 (io), M16 I/O186 HX2 (io), M20 I/O187 HX3 (io), M21 I/O185 HX1 (io), M22 I/O184 HX0 (io), N16 I/O162 EX2 (io), N19 I/O190 HX6 (io), N20 I/O191 HX7 (io), N21 I/O189 HX5 (io), N22 I/O188 HX4 (io), P20 I/O163 EX3 (io), P21 I/O161 EX1 (io), P22 I/O160 EX0 (io), R19 I/O177 GX1 (io), R20 I/O166 EX6 (io), R21 I/O165 EX5 (io), R22 I/O164 EX4 (io), T12 I/O131 AX3 (io), T13 I/O152 DX0 (io), T19 I/O181 GX5 (io), T20 I/O179 GX3 (io), T21 I/O176 GX0 (io), T22 I/O167 EX7 (io), U20 I/O183 GX7 (io), U21 I/O180 GX4 (io), U22 I/O178 GX2 (io), V19 I/O172 FX4 (io), V20 I/O169 FX1 (io), V22 I/O182 GX6 (io), W13 I/O153 DX1 (io), W15 I/O145 CX1 (io), W16 I/O150 CX6 (io), W18 I/O143 BX7 (io), W20 I/O173 FX5 (io), W21 I/O170 FX2 (io), W22 I/O168 FX0 (io), Y12 I/O132 AX4 (io), Y14 I/O156 DX4 (io), Y15 I/O158 DX6 (io), Y16 I/O147 CX3 (io), Y17 I/O136 BX0 (io), Y18 I/O138 BX2 (io), Y19 I/O141 BX5 (io), Y21 I/O174 FX6 (io), Y22 I/O171 FX3 (io)
part C pins: A1 GND (power), A2 NC, A22 GND (power), AA1 TCK (in), AA2 GND (power), AA10 CLK1 (in), AA21 GND (power), AB1 GND (power), AB21 NC, AB22 GND (power), B1 TDI (in), B2 GND (power), B10 CLK0 (in), B21 GND (power), B22 NC, C3 GND (power), C13 CLK3 (in), C20 GND (power), C21 TDO (out), D4 GND (power), D6 VCC (power), D9 VCC (power), D12 VCC (power), D14 VCC (power), D17 VCC (power), D19 GND (power), F4 VCC (power), F19 VCC (power), G7 VCC (power), G8 VCC (power), G9 NC, G14 NC, G15 VCC (power), G16 VCC (power), H7 VCC (power), H8 NC, H9 GND (power), H10 GND (power), H11 GND (power), H12 GND (power), H13 GND (power), H14 GND (power), H15 NC, H16 VCC (power), J4 VCC (power), J7 NC, J8 GND (power), J9 GND (power), J10 GND (power), J11 GND (power), J12 GND (power), J13 GND (power), J14 GND (power), J15 GND (power), J16 NC, J19 VCC (power), K8 GND (power), K9 GND (power), K10 GND (power), K11 GND (power), K12 GND (power), K13 GND (power), K14 GND (power), K15 GND (power), L4 VCC (power), L8 GND (power), L9 GND (power), L10 GND (power), L11 GND (power), L12 GND (power), L13 GND (power), L14 GND (power), L15 GND (power), M8 GND (power), M9 GND (power), M10 GND (power), M11 GND (power), M12 GND (power), M13 GND (power), M14 GND (power), M15 GND (power), M19 VCC (power), N8 GND (power), N9 GND (power), N10 GND (power), N11 GND (power), N12 GND (power), N13 GND (power), N14 GND (power), N15 GND (power), P4 VCC (power), P7 NC, P8 GND (power), P9 GND (power), P10 GND (power), P11 GND (power), P12 GND (power), P13 GND (power), P14 GND (power), P15 GND (power), P16 NC, P19 VCC (power), R7 VCC (power), R8 NC, R9 GND (power), R10 GND (power), R11 GND (power), R12 GND (power), R13 GND (power), R14 GND (power), R15 NC, R16 VCC (power), T7 VCC (power), T8 VCC (power), T9 NC, T14 NC, T15 VCC (power), T16 VCC (power), U4 VCC (power), U19 VCC (power), V21 NC, W4 GND (power), W6 VCC (power), W9 VCC (power), W11 VCC (power), W14 VCC (power), W17 VCC (power), W19 GND (power), Y2 TMS (in), Y3 GND (power), Y13 CLK2 (in), Y20 GND (power)

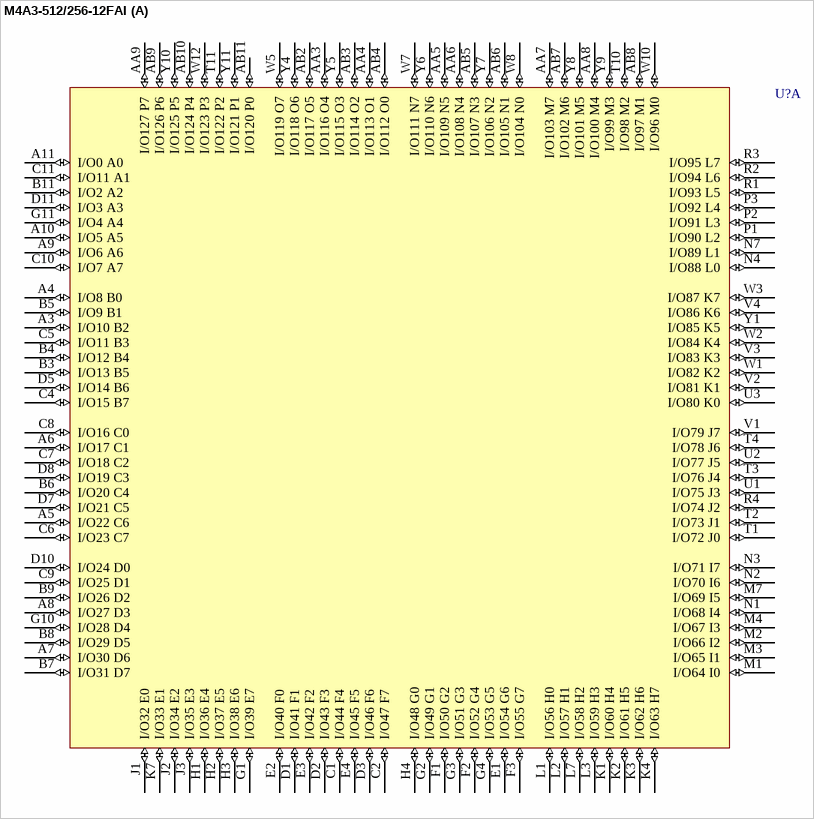
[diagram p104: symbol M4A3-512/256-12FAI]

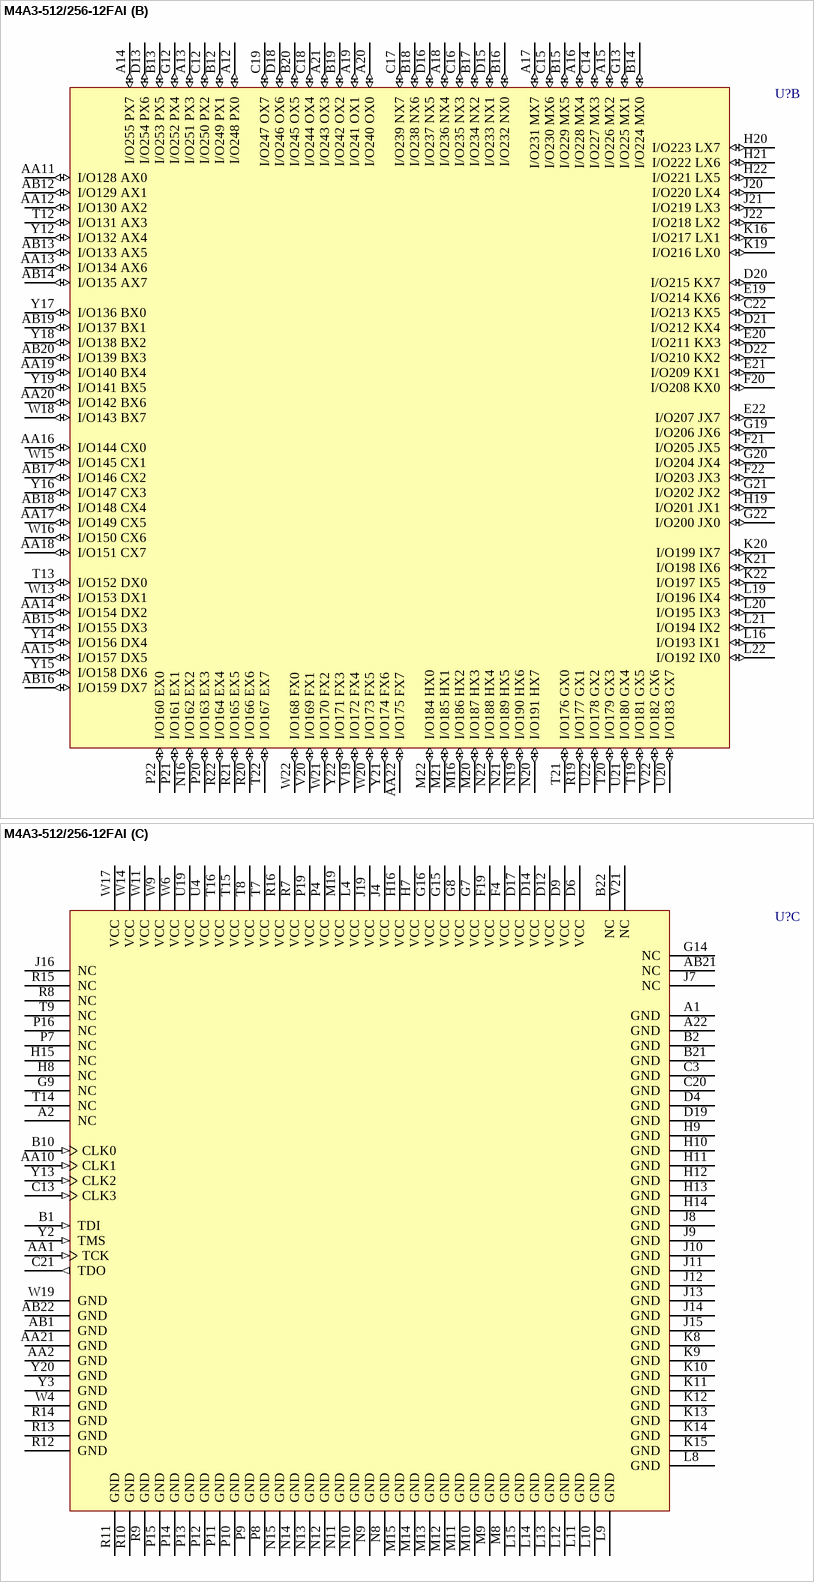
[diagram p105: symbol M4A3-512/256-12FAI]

## M4A3-512/256-12FAI
designator U?
High-Performance EE CMOS In-System Programmable Logic
footprint fpBGA388 (BGA, 388-Leads, Body 23x23mm, Pitch 1mm)
3D model M4A3-fpBGA388 (388-Ball Fine Pitch Ball Grid Array (fpBGA388))
part A pins: A3 I/O10 B2 (io), A4 I/O8 B0 (io), A5 I/O22 C6 (io), A6 I/O17 C1 (io), A7 I/O30 D6 (io), A8 I/O27 D3 (io), A9 I/O6 A6 (io), A10 I/O5 A5 (io), A11 I/O0 A0 (io), AA3 I/O116 O4 (io), AA4 I/O113 O1 (io), AA5 I/O109 N5 (io), AA6 I/O108 N4 (io), AA7 I/O103 M7 (io), AA8 I/O100 M4 (io), AA9 I/O127 P7 (io), AB2 I/O117 O5 (io), AB3 I/O114 O2 (io), AB4 I/O112 O0 (io), AB5 I/O107 N3 (io), AB6 I/O105 N1 (io), AB7 I/O102 M6 (io), AB8 I/O97 M1 (io), AB9 I/O126 P6 (io), AB10 I/O124 P4 (io), AB11 I/O120 P0 (io), B3 I/O13 B5 (io), B4 I/O12 B4 (io), B5 I/O9 B1 (io), B6 I/O20 C4 (io), B7 I/O31 D7 (io), B8 I/O29 D5 (io), B9 I/O26 D2 (io), B11 I/O2 A2 (io), C1 I/O44 F4 (io), C2 I/O47 F7 (io), C4 I/O15 B7 (io), C5 I/O11 B3 (io), C6 I/O23 C7 (io), C7 I/O18 C2 (io), C8 I/O16 C0 (io), C9 I/O25 D1 (io), C10 I/O7 A7 (io), C11 I/O11 A1 (io), D1 I/O41 F1 (io), D2 I/O43 F3 (io), D3 I/O46 F6 (io), D5 I/O14 B6 (io), D7 I/O21 C5 (io), D8 I/O19 C3 (io), D10 I/O24 D0 (io), D11 I/O3 A3 (io), E1 I/O54 G6 (io), E2 I/O40 F0 (io), E3 I/O42 F2 (io), E4 I/O45 F5 (io), F1 I/O50 G2 (io), F2 I/O52 G4 (io), F3 I/O55 G7 (io), G1 I/O39 E7 (io), G2 I/O49 G1 (io), G3 I/O51 G3 (io), G4 I/O53 G5 (io), G10 I/O28 D4 (io), G11 I/O4 A4 (io), H1 I/O36 E4 (io), H2 I/O37 E5 (io), H3 I/O38 E6 (io), H4 I/O48 G0 (io), J1 I/O32 E0 (io), J2 I/O34 E2 (io), J3 I/O35 E3 (io), K1 I/O60 H4 (io), K2 I/O61 H5 (io), K3 I/O62 H6 (io), K4 I/O63 H7 (io), K7 I/O33 E1 (io), L1 I/O56 H0 (io), L2 I/O57 H1 (io), L3 I/O59 H3 (io), L7 I/O58 H2 (io), M1 I/O64 I0 (io), M2 I/O66 I2 (io), M3 I/O65 I1 (io), M4 I/O67 I3 (io), M7 I/O69 I5 (io), N1 I/O68 I4 (io), N2 I/O70 I6 (io), N3 I/O71 I7 (io), N4 I/O88 L0 (io), N7 I/O89 L1 (io), P1 I/O90 L2 (io), P2 I/O91 L3 (io), P3 I/O92 L4 (io), R1 I/O93 L5 (io), R2 I/O94 L6 (io), R3 I/O95 L7 (io), R4 I/O74 J2 (io), T1 I/O72 J0 (io), T2 I/O73 J1 (io), T3 I/O76 J4 (io), T4 I/O78 J6 (io), T10 I/O98 M2 (io), T11 I/O122 P2 (io), U1 I/O75 J3 (io), U2 I/O77 J5 (io), U3 I/O80 K0 (io), V1 I/O79 J7 (io), V2 I/O81 K1 (io), V3 I/O83 K3 (io), V4 I/O86 K6 (io), W1 I/O82 K2 (io), W2 I/O84 K4 (io), W3 I/O87 K7 (io), W5 I/O119 O7 (io), W7 I/O111 N7 (io), W8 I/O104 N0 (io), W10 I/O96 M0 (io), W12 I/O123 P3 (io), Y1 I/O85 K5 (io), Y4 I/O118 O6 (io), Y5 I/O115 O3 (io), Y6 I/O110 N6 (io), Y7 I/O106 N2 (io), Y8 I/O101 M5 (io), Y9 I/O99 M3 (io), Y10 I/O125 P5 (io), Y11 I/O121 P1 (io)
part B pins: A12 I/O248 PX0 (io), A13 I/O251 PX3 (io), A14 I/O255 PX7 (io), A15 I/O226 MX2 (io), A16 I/O228 MX4 (io), A17 I/O231 MX7 (io), A18 I/O236 NX4 (io), A19 I/O241 OX1 (io), A20 I/O240 OX0 (io), A21 I/O243 OX3 (io), AA11 I/O128 AX0 (io), AA12 I/O130 AX2 (io), AA13 I/O134 AX6 (io), AA14 I/O154 DX2 (io), AA15 I/O157 DX5 (io), AA16 I/O144 CX0 (io), AA17 I/O149 CX5 (io), AA18 I/O151 CX7 (io), AA19 I/O140 BX4 (io), AA20 I/O142 BX6 (io), AA22 I/O175 FX7 (io), AB12 I/O129 AX1 (io), AB13 I/O133 AX5 (io), AB14 I/O135 AX7 (io), AB15 I/O155 DX3 (io), AB16 I/O159 DX7 (io), AB17 I/O146 CX2 (io), AB18 I/O148 CX4 (io), AB19 I/O137 BX1 (io), AB20 I/O139 BX3 (io), B12 I/O249 PX1 (io), B13 I/O253 PX5 (io), B14 I/O224 MX0 (io), B15 I/O229 MX5 (io), B16 I/O232 NX0 (io), B17 I/O234 NX2 (io), B18 I/O238 NX6 (io), B19 I/O242 OX2 (io), B20 I/O245 OX5 (io), C12 I/O250 PX2 (io), C14 I/O227 MX3 (io), C15 I/O230 MX6 (io), C16 I/O235 NX3 (io), C17 I/O239 NX7 (io), C18 I/O244 OX4 (io), C19 I/O247 OX7 (io), C22 I/O213 KX5 (io), D13 I/O254 PX6 (io), D15 I/O233 NX1 (io), D16 I/O237 NX5 (io), D18 I/O246 OX6 (io), D20 I/O215 KX7 (io), D21 I/O212 KX4 (io), D22 I/O210 KX2 (io), E19 I/O214 KX6 (io), E20 I/O211 KX3 (io), E21 I/O209 KX1 (io), E22 I/O207 JX7 (io), F20 I/O208 KX0 (io), F21 I/O205 JX5 (io), F22 I/O203 JX3 (io), G12 I/O252 PX4 (io), G13 I/O225 MX1 (io), G19 I/O206 JX6 (io), G20 I/O204 JX4 (io), G21 I/O202 JX2 (io), G22 I/O200 JX0 (io), H19 I/O201 JX1 (io), H20 I/O223 LX7 (io), H21 I/O222 LX6 (io), H22 I/O221 LX5 (io), J20 I/O220 LX4 (io), J21 I/O219 LX3 (io), J22 I/O218 LX2 (io), K16 I/O217 LX1 (io), K19 I/O216 LX0 (io), K20 I/O199 IX7 (io), K21 I/O198 IX6 (io), K22 I/O197 IX5 (io), L16 I/O193 IX1 (io), L19 I/O196 IX4 (io), L20 I/O195 IX3 (io), L21 I/O194 IX2 (io), L22 I/O192 IX0 (io), M16 I/O186 HX2 (io), M20 I/O187 HX3 (io), M21 I/O185 HX1 (io), M22 I/O184 HX0 (io), N16 I/O162 EX2 (io), N19 I/O190 HX6 (io), N20 I/O191 HX7 (io), N21 I/O189 HX5 (io), N22 I/O188 HX4 (io), P20 I/O163 EX3 (io), P21 I/O161 EX1 (io), P22 I/O160 EX0 (io), R19 I/O177 GX1 (io), R20 I/O166 EX6 (io), R21 I/O165 EX5 (io), R22 I/O164 EX4 (io), T12 I/O131 AX3 (io), T13 I/O152 DX0 (io), T19 I/O181 GX5 (io), T20 I/O179 GX3 (io), T21 I/O176 GX0 (io), T22 I/O167 EX7 (io), U20 I/O183 GX7 (io), U21 I/O180 GX4 (io), U22 I/O178 GX2 (io), V19 I/O172 FX4 (io), V20 I/O169 FX1 (io), V22 I/O182 GX6 (io), W13 I/O153 DX1 (io), W15 I/O145 CX1 (io), W16 I/O150 CX6 (io), W18 I/O143 BX7 (io), W20 I/O173 FX5 (io), W21 I/O170 FX2 (io), W22 I/O168 FX0 (io), Y12 I/O132 AX4 (io), Y14 I/O156 DX4 (io), Y15 I/O158 DX6 (io), Y16 I/O147 CX3 (io), Y17 I/O136 BX0 (io), Y18 I/O138 BX2 (io), Y19 I/O141 BX5 (io), Y21 I/O174 FX6 (io), Y22 I/O171 FX3 (io)
part C pins: A1 GND (power), A2 NC, A22 GND (power), AA1 TCK (in), AA2 GND (power), AA10 CLK1 (in), AA21 GND (power), AB1 GND (power), AB21 NC, AB22 GND (power), B1 TDI (in), B2 GND (power), B10 CLK0 (in), B21 GND (power), B22 NC, C3 GND (power), C13 CLK3 (in), C20 GND (power), C21 TDO (out), D4 GND (power), D6 VCC (power), D9 VCC (power), D12 VCC (power), D14 VCC (power), D17 VCC (power), D19 GND (power), F4 VCC (power), F19 VCC (power), G7 VCC (power), G8 VCC (power), G9 NC, G14 NC, G15 VCC (power), G16 VCC (power), H7 VCC (power), H8 NC, H9 GND (power), H10 GND (power), H11 GND (power), H12 GND (power), H13 GND (power), H14 GND (power), H15 NC, H16 VCC (power), J4 VCC (power), J7 NC, J8 GND (power), J9 GND (power), J10 GND (power), J11 GND (power), J12 GND (power), J13 GND (power), J14 GND (power), J15 GND (power), J16 NC, J19 VCC (power), K8 GND (power), K9 GND (power), K10 GND (power), K11 GND (power), K12 GND (power), K13 GND (power), K14 GND (power), K15 GND (power), L4 VCC (power), L8 GND (power), L9 GND (power), L10 GND (power), L11 GND (power), L12 GND (power), L13 GND (power), L14 GND (power), L15 GND (power), M8 GND (power), M9 GND (power), M10 GND (power), M11 GND (power), M12 GND (power), M13 GND (power), M14 GND (power), M15 GND (power), M19 VCC (power), N8 GND (power), N9 GND (power), N10 GND (power), N11 GND (power), N12 GND (power), N13 GND (power), N14 GND (power), N15 GND (power), P4 VCC (power), P7 NC, P8 GND (power), P9 GND (power), P10 GND (power), P11 GND (power), P12 GND (power), P13 GND (power), P14 GND (power), P15 GND (power), P16 NC, P19 VCC (power), R7 VCC (power), R8 NC, R9 GND (power), R10 GND (power), R11 GND (power), R12 GND (power), R13 GND (power), R14 GND (power), R15 NC, R16 VCC (power), T7 VCC (power), T8 VCC (power), T9 NC, T14 NC, T15 VCC (power), T16 VCC (power), U4 VCC (power), U19 VCC (power), V21 NC, W4 GND (power), W6 VCC (power), W9 VCC (power), W11 VCC (power), W14 VCC (power), W17 VCC (power), W19 GND (power), Y2 TMS (in), Y3 GND (power), Y13 CLK2 (in), Y20 GND (power)

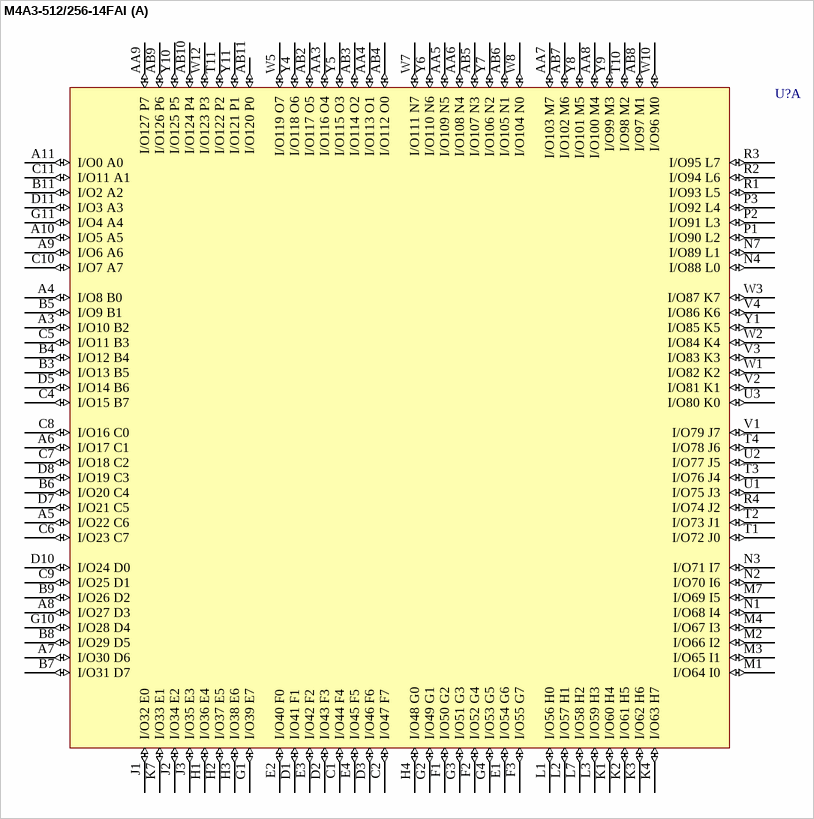
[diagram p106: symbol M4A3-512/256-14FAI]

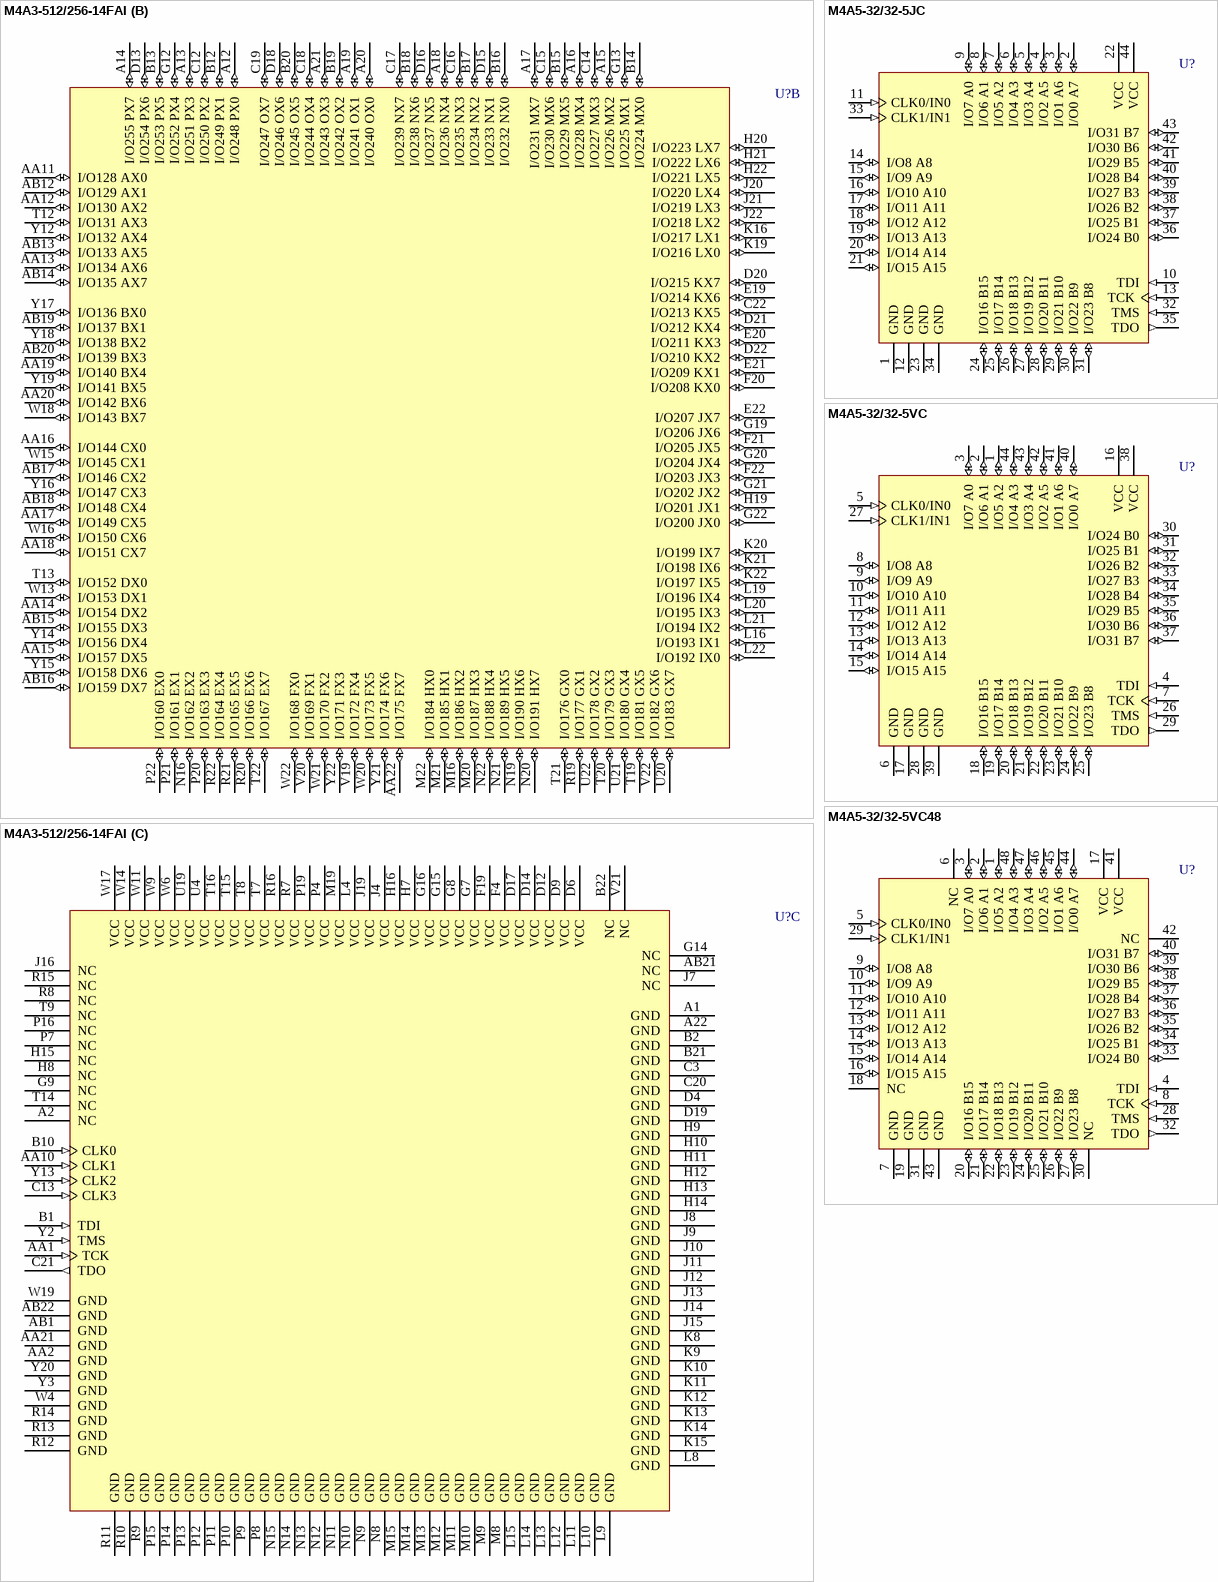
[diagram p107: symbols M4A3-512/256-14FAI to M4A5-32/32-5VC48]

## M4A3-512/256-14FAI
designator U?
High-Performance EE CMOS In-System Programmable Logic
footprint fpBGA388 (BGA, 388-Leads, Body 23x23mm, Pitch 1mm)
3D model M4A3-fpBGA388 (388-Ball Fine Pitch Ball Grid Array (fpBGA388))
part A pins: A3 I/O10 B2 (io), A4 I/O8 B0 (io), A5 I/O22 C6 (io), A6 I/O17 C1 (io), A7 I/O30 D6 (io), A8 I/O27 D3 (io), A9 I/O6 A6 (io), A10 I/O5 A5 (io), A11 I/O0 A0 (io), AA3 I/O116 O4 (io), AA4 I/O113 O1 (io), AA5 I/O109 N5 (io), AA6 I/O108 N4 (io), AA7 I/O103 M7 (io), AA8 I/O100 M4 (io), AA9 I/O127 P7 (io), AB2 I/O117 O5 (io), AB3 I/O114 O2 (io), AB4 I/O112 O0 (io), AB5 I/O107 N3 (io), AB6 I/O105 N1 (io), AB7 I/O102 M6 (io), AB8 I/O97 M1 (io), AB9 I/O126 P6 (io), AB10 I/O124 P4 (io), AB11 I/O120 P0 (io), B3 I/O13 B5 (io), B4 I/O12 B4 (io), B5 I/O9 B1 (io), B6 I/O20 C4 (io), B7 I/O31 D7 (io), B8 I/O29 D5 (io), B9 I/O26 D2 (io), B11 I/O2 A2 (io), C1 I/O44 F4 (io), C2 I/O47 F7 (io), C4 I/O15 B7 (io), C5 I/O11 B3 (io), C6 I/O23 C7 (io), C7 I/O18 C2 (io), C8 I/O16 C0 (io), C9 I/O25 D1 (io), C10 I/O7 A7 (io), C11 I/O11 A1 (io), D1 I/O41 F1 (io), D2 I/O43 F3 (io), D3 I/O46 F6 (io), D5 I/O14 B6 (io), D7 I/O21 C5 (io), D8 I/O19 C3 (io), D10 I/O24 D0 (io), D11 I/O3 A3 (io), E1 I/O54 G6 (io), E2 I/O40 F0 (io), E3 I/O42 F2 (io), E4 I/O45 F5 (io), F1 I/O50 G2 (io), F2 I/O52 G4 (io), F3 I/O55 G7 (io), G1 I/O39 E7 (io), G2 I/O49 G1 (io), G3 I/O51 G3 (io), G4 I/O53 G5 (io), G10 I/O28 D4 (io), G11 I/O4 A4 (io), H1 I/O36 E4 (io), H2 I/O37 E5 (io), H3 I/O38 E6 (io), H4 I/O48 G0 (io), J1 I/O32 E0 (io), J2 I/O34 E2 (io), J3 I/O35 E3 (io), K1 I/O60 H4 (io), K2 I/O61 H5 (io), K3 I/O62 H6 (io), K4 I/O63 H7 (io), K7 I/O33 E1 (io), L1 I/O56 H0 (io), L2 I/O57 H1 (io), L3 I/O59 H3 (io), L7 I/O58 H2 (io), M1 I/O64 I0 (io), M2 I/O66 I2 (io), M3 I/O65 I1 (io), M4 I/O67 I3 (io), M7 I/O69 I5 (io), N1 I/O68 I4 (io), N2 I/O70 I6 (io), N3 I/O71 I7 (io), N4 I/O88 L0 (io), N7 I/O89 L1 (io), P1 I/O90 L2 (io), P2 I/O91 L3 (io), P3 I/O92 L4 (io), R1 I/O93 L5 (io), R2 I/O94 L6 (io), R3 I/O95 L7 (io), R4 I/O74 J2 (io), T1 I/O72 J0 (io), T2 I/O73 J1 (io), T3 I/O76 J4 (io), T4 I/O78 J6 (io), T10 I/O98 M2 (io), T11 I/O122 P2 (io), U1 I/O75 J3 (io), U2 I/O77 J5 (io), U3 I/O80 K0 (io), V1 I/O79 J7 (io), V2 I/O81 K1 (io), V3 I/O83 K3 (io), V4 I/O86 K6 (io), W1 I/O82 K2 (io), W2 I/O84 K4 (io), W3 I/O87 K7 (io), W5 I/O119 O7 (io), W7 I/O111 N7 (io), W8 I/O104 N0 (io), W10 I/O96 M0 (io), W12 I/O123 P3 (io), Y1 I/O85 K5 (io), Y4 I/O118 O6 (io), Y5 I/O115 O3 (io), Y6 I/O110 N6 (io), Y7 I/O106 N2 (io), Y8 I/O101 M5 (io), Y9 I/O99 M3 (io), Y10 I/O125 P5 (io), Y11 I/O121 P1 (io)
part B pins: A12 I/O248 PX0 (io), A13 I/O251 PX3 (io), A14 I/O255 PX7 (io), A15 I/O226 MX2 (io), A16 I/O228 MX4 (io), A17 I/O231 MX7 (io), A18 I/O236 NX4 (io), A19 I/O241 OX1 (io), A20 I/O240 OX0 (io), A21 I/O243 OX3 (io), AA11 I/O128 AX0 (io), AA12 I/O130 AX2 (io), AA13 I/O134 AX6 (io), AA14 I/O154 DX2 (io), AA15 I/O157 DX5 (io), AA16 I/O144 CX0 (io), AA17 I/O149 CX5 (io), AA18 I/O151 CX7 (io), AA19 I/O140 BX4 (io), AA20 I/O142 BX6 (io), AA22 I/O175 FX7 (io), AB12 I/O129 AX1 (io), AB13 I/O133 AX5 (io), AB14 I/O135 AX7 (io), AB15 I/O155 DX3 (io), AB16 I/O159 DX7 (io), AB17 I/O146 CX2 (io), AB18 I/O148 CX4 (io), AB19 I/O137 BX1 (io), AB20 I/O139 BX3 (io), B12 I/O249 PX1 (io), B13 I/O253 PX5 (io), B14 I/O224 MX0 (io), B15 I/O229 MX5 (io), B16 I/O232 NX0 (io), B17 I/O234 NX2 (io), B18 I/O238 NX6 (io), B19 I/O242 OX2 (io), B20 I/O245 OX5 (io), C12 I/O250 PX2 (io), C14 I/O227 MX3 (io), C15 I/O230 MX6 (io), C16 I/O235 NX3 (io), C17 I/O239 NX7 (io), C18 I/O244 OX4 (io), C19 I/O247 OX7 (io), C22 I/O213 KX5 (io), D13 I/O254 PX6 (io), D15 I/O233 NX1 (io), D16 I/O237 NX5 (io), D18 I/O246 OX6 (io), D20 I/O215 KX7 (io), D21 I/O212 KX4 (io), D22 I/O210 KX2 (io), E19 I/O214 KX6 (io), E20 I/O211 KX3 (io), E21 I/O209 KX1 (io), E22 I/O207 JX7 (io), F20 I/O208 KX0 (io), F21 I/O205 JX5 (io), F22 I/O203 JX3 (io), G12 I/O252 PX4 (io), G13 I/O225 MX1 (io), G19 I/O206 JX6 (io), G20 I/O204 JX4 (io), G21 I/O202 JX2 (io), G22 I/O200 JX0 (io), H19 I/O201 JX1 (io), H20 I/O223 LX7 (io), H21 I/O222 LX6 (io), H22 I/O221 LX5 (io), J20 I/O220 LX4 (io), J21 I/O219 LX3 (io), J22 I/O218 LX2 (io), K16 I/O217 LX1 (io), K19 I/O216 LX0 (io), K20 I/O199 IX7 (io), K21 I/O198 IX6 (io), K22 I/O197 IX5 (io), L16 I/O193 IX1 (io), L19 I/O196 IX4 (io), L20 I/O195 IX3 (io), L21 I/O194 IX2 (io), L22 I/O192 IX0 (io), M16 I/O186 HX2 (io), M20 I/O187 HX3 (io), M21 I/O185 HX1 (io), M22 I/O184 HX0 (io), N16 I/O162 EX2 (io), N19 I/O190 HX6 (io), N20 I/O191 HX7 (io), N21 I/O189 HX5 (io), N22 I/O188 HX4 (io), P20 I/O163 EX3 (io), P21 I/O161 EX1 (io), P22 I/O160 EX0 (io), R19 I/O177 GX1 (io), R20 I/O166 EX6 (io), R21 I/O165 EX5 (io), R22 I/O164 EX4 (io), T12 I/O131 AX3 (io), T13 I/O152 DX0 (io), T19 I/O181 GX5 (io), T20 I/O179 GX3 (io), T21 I/O176 GX0 (io), T22 I/O167 EX7 (io), U20 I/O183 GX7 (io), U21 I/O180 GX4 (io), U22 I/O178 GX2 (io), V19 I/O172 FX4 (io), V20 I/O169 FX1 (io), V22 I/O182 GX6 (io), W13 I/O153 DX1 (io), W15 I/O145 CX1 (io), W16 I/O150 CX6 (io), W18 I/O143 BX7 (io), W20 I/O173 FX5 (io), W21 I/O170 FX2 (io), W22 I/O168 FX0 (io), Y12 I/O132 AX4 (io), Y14 I/O156 DX4 (io), Y15 I/O158 DX6 (io), Y16 I/O147 CX3 (io), Y17 I/O136 BX0 (io), Y18 I/O138 BX2 (io), Y19 I/O141 BX5 (io), Y21 I/O174 FX6 (io), Y22 I/O171 FX3 (io)
part C pins: A1 GND (power), A2 NC, A22 GND (power), AA1 TCK (in), AA2 GND (power), AA10 CLK1 (in), AA21 GND (power), AB1 GND (power), AB21 NC, AB22 GND (power), B1 TDI (in), B2 GND (power), B10 CLK0 (in), B21 GND (power), B22 NC, C3 GND (power), C13 CLK3 (in), C20 GND (power), C21 TDO (out), D4 GND (power), D6 VCC (power), D9 VCC (power), D12 VCC (power), D14 VCC (power), D17 VCC (power), D19 GND (power), F4 VCC (power), F19 VCC (power), G7 VCC (power), G8 VCC (power), G9 NC, G14 NC, G15 VCC (power), G16 VCC (power), H7 VCC (power), H8 NC, H9 GND (power), H10 GND (power), H11 GND (power), H12 GND (power), H13 GND (power), H14 GND (power), H15 NC, H16 VCC (power), J4 VCC (power), J7 NC, J8 GND (power), J9 GND (power), J10 GND (power), J11 GND (power), J12 GND (power), J13 GND (power), J14 GND (power), J15 GND (power), J16 NC, J19 VCC (power), K8 GND (power), K9 GND (power), K10 GND (power), K11 GND (power), K12 GND (power), K13 GND (power), K14 GND (power), K15 GND (power), L4 VCC (power), L8 GND (power), L9 GND (power), L10 GND (power), L11 GND (power), L12 GND (power), L13 GND (power), L14 GND (power), L15 GND (power), M8 GND (power), M9 GND (power), M10 GND (power), M11 GND (power), M12 GND (power), M13 GND (power), M14 GND (power), M15 GND (power), M19 VCC (power), N8 GND (power), N9 GND (power), N10 GND (power), N11 GND (power), N12 GND (power), N13 GND (power), N14 GND (power), N15 GND (power), P4 VCC (power), P7 NC, P8 GND (power), P9 GND (power), P10 GND (power), P11 GND (power), P12 GND (power), P13 GND (power), P14 GND (power), P15 GND (power), P16 NC, P19 VCC (power), R7 VCC (power), R8 NC, R9 GND (power), R10 GND (power), R11 GND (power), R12 GND (power), R13 GND (power), R14 GND (power), R15 NC, R16 VCC (power), T7 VCC (power), T8 VCC (power), T9 NC, T14 NC, T15 VCC (power), T16 VCC (power), U4 VCC (power), U19 VCC (power), V21 NC, W4 GND (power), W6 VCC (power), W9 VCC (power), W11 VCC (power), W14 VCC (power), W17 VCC (power), W19 GND (power), Y2 TMS (in), Y3 GND (power), Y13 CLK2 (in), Y20 GND (power)

## M4A5-32/32-5JC
designator U?
High-Performance EE CMOS In-System Programmable Logic
footprint PLCC44_N (Leaded Chip Carrier, 44-Leads, Body 16.6x16.6mm, Pitch 1.27mm, IPC Medium Density)
footprint PLCC44_L (Leaded Chip Carrier, 44-Leads, Body 16.6x16.6mm, Pitch 1.27mm, IPC High Density)
footprint PLCC44_M (Leaded Chip Carrier, 44-Leads, Body 16.6x16.6mm, Pitch 1.27mm, IPC Low Density)
3D model M4A5-PLCC44 (44-Pin Leaded Chip Carrier 1.27 mm Pitch)
pins: 1 GND (power), 2 I/O0 A7 (io), 3 I/O1 A6 (io), 4 I/O2 A5 (io), 5 I/O3 A4 (io), 6 I/O4 A3 (io), 7 I/O5 A2 (io), 8 I/O6 A1 (io), 9 I/O7 A0 (io), 10 TDI (in), 11 CLK0/IN0 (in), 12 GND (power), 13 TCK (in), 14 I/O8 A8 (io), 15 I/O9 A9 (io), 16 I/O10 A10 (io), 17 I/O11 A11 (io), 18 I/O12 A12 (io), 19 I/O13 A13 (io), 20 I/O14 A14 (io), 21 I/O15 A15 (io), 22 VCC (power), 23 GND (power), 24 I/O16 B15 (io), 25 I/O17 B14 (io), 26 I/O18 B13 (io), 27 I/O19 B12 (io), 28 I/O20 B11 (io), 29 I/O21 B10 (io), 30 I/O22 B9 (io), 31 I/O23 B8 (io), 32 TMS (in), 33 CLK1/IN1 (in), 34 GND (power), 35 TDO (out), 36 I/O24 B0 (io), 37 I/O25 B1 (io), 38 I/O26 B2 (io), 39 I/O27 B3 (io), 40 I/O28 B4 (io), 41 I/O29 B5 (io), 42 I/O30 B6 (io), 43 I/O31 B7 (io), 44 VCC (power)

## M4A5-32/32-5VC
designator U?
High-Performance EE CMOS In-System Programmable Logic
footprint TQFP44_N (Thin QFP, 44-Leads, Body 10x10mm, Pitch 0.8mm, IPC Medium Density)
footprint TQFP44_L (Thin QFP, 44-Leads, Body 10x10mm, Pitch 0.8mm, IPC High Density)
footprint TQFP44_M (Thin QFP, 44-Leads, Body 10x10mm, Pitch 0.8mm, IPC Low Density)
3D model M4A5-TQFP44 (44-Pin Thin Quad Flat Pack 0.8 mm Pitch)
pins: 1 I/O5 A2 (io), 2 I/O6 A1 (io), 3 I/O7 A0 (io), 4 TDI (in), 5 CLK0/IN0 (in), 6 GND (power), 7 TCK (in), 8 I/O8 A8 (io), 9 I/O9 A9 (io), 10 I/O10 A10 (io), 11 I/O11 A11 (io), 12 I/O12 A12 (io), 13 I/O13 A13 (io), 14 I/O14 A14 (io), 15 I/O15 A15 (io), 16 VCC (power), 17 GND (power), 18 I/O16 B15 (io), 19 I/O17 B14 (io), 20 I/O18 B13 (io), 21 I/O19 B12 (io), 22 I/O20 B11 (io), 23 I/O21 B10 (io), 24 I/O22 B9 (io), 25 I/O23 B8 (io), 26 TMS (in), 27 CLK1/IN1 (in), 28 GND (power), 29 TDO (out), 30 I/O24 B0 (io), 31 I/O25 B1 (io), 32 I/O26 B2 (io), 33 I/O27 B3 (io), 34 I/O28 B4 (io), 35 I/O29 B5 (io), 36 I/O30 B6 (io), 37 I/O31 B7 (io), 38 VCC (power), 39 GND (power), 40 I/O0 A7 (io), 41 I/O1 A6 (io), 42 I/O2 A5 (io), 43 I/O3 A4 (io), 44 I/O4 A3 (io)

## M4A5-32/32-5VC48
designator U?
High-Performance EE CMOS In-System Programmable Logic
footprint TQFP48_N (Thin QFP, 48-Leads, Body 7x7mm, Pitch 0.5mm, IPC Medium Density)
footprint TQFP48_L (Thin QFP, 48-Leads, Body 7x7mm, Pitch 0.5mm, IPC High Density)
footprint TQFP48_M (Thin QFP, 48-Leads, Body 7x7mm, Pitch 0.5mm, IPC Low Density)
3D model M4A5-TQFP48 (48-Pin Thin Quad Flat Pack 0.5 mm Pitch)
pins: 1 I/O5 A2 (io), 2 I/O6 A1 (io), 3 I/O7 A0 (io), 4 TDI (in), 5 CLK0/IN0 (in), 6 NC, 7 GND (power), 8 TCK (in), 9 I/O8 A8 (io), 10 I/O9 A9 (io), 11 I/O10 A10 (io), 12 I/O11 A11 (io), 13 I/O12 A12 (io), 14 I/O13 A13 (io), 15 I/O14 A14 (io), 16 I/O15 A15 (io), 17 VCC (power), 18 NC, 19 GND (power), 20 I/O16 B15 (io), 21 I/O17 B14 (io), 22 I/O18 B13 (io), 23 I/O19 B12 (io), 24 I/O20 B11 (io), 25 I/O21 B10 (io), 26 I/O22 B9 (io), 27 I/O23 B8 (io), 28 TMS (in), 29 CLK1/IN1 (in), 30 NC, 31 GND (power), 32 TDO (out), 33 I/O24 B0 (io), 34 I/O25 B1 (io), 35 I/O26 B2 (io), 36 I/O27 B3 (io), 37 I/O28 B4 (io), 38 I/O29 B5 (io), 39 I/O30 B6 (io), 40 I/O31 B7 (io), 41 VCC (power), 42 NC, 43 GND (power), 44 I/O0 A7 (io), 45 I/O1 A6 (io), 46 I/O2 A5 (io), 47 I/O3 A4 (io), 48 I/O4 A3 (io)

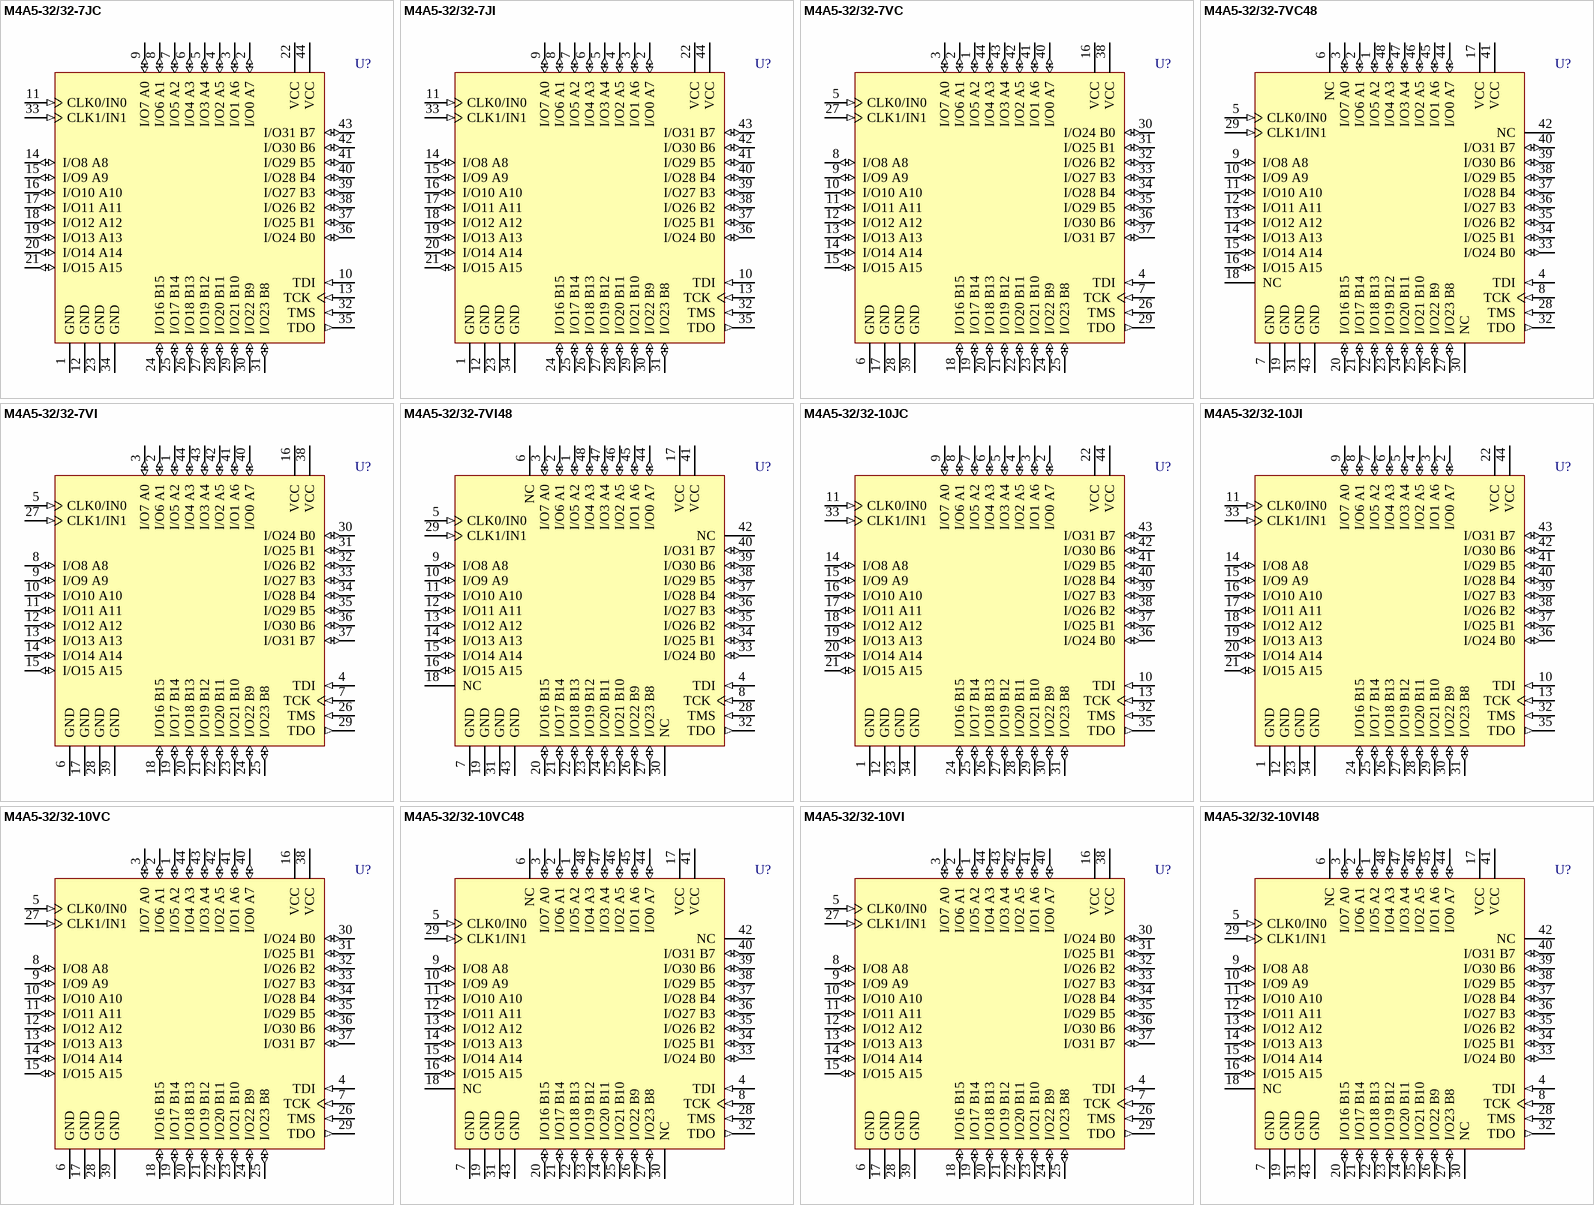
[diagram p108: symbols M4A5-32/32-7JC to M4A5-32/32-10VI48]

## M4A5-32/32-7JC
designator U?
High-Performance EE CMOS In-System Programmable Logic
footprint PLCC44_N (Leaded Chip Carrier, 44-Leads, Body 16.6x16.6mm, Pitch 1.27mm, IPC Medium Density)
footprint PLCC44_L (Leaded Chip Carrier, 44-Leads, Body 16.6x16.6mm, Pitch 1.27mm, IPC High Density)
footprint PLCC44_M (Leaded Chip Carrier, 44-Leads, Body 16.6x16.6mm, Pitch 1.27mm, IPC Low Density)
3D model M4A5-PLCC44 (44-Pin Leaded Chip Carrier 1.27 mm Pitch)
pins: 1 GND (power), 2 I/O0 A7 (io), 3 I/O1 A6 (io), 4 I/O2 A5 (io), 5 I/O3 A4 (io), 6 I/O4 A3 (io), 7 I/O5 A2 (io), 8 I/O6 A1 (io), 9 I/O7 A0 (io), 10 TDI (in), 11 CLK0/IN0 (in), 12 GND (power), 13 TCK (in), 14 I/O8 A8 (io), 15 I/O9 A9 (io), 16 I/O10 A10 (io), 17 I/O11 A11 (io), 18 I/O12 A12 (io), 19 I/O13 A13 (io), 20 I/O14 A14 (io), 21 I/O15 A15 (io), 22 VCC (power), 23 GND (power), 24 I/O16 B15 (io), 25 I/O17 B14 (io), 26 I/O18 B13 (io), 27 I/O19 B12 (io), 28 I/O20 B11 (io), 29 I/O21 B10 (io), 30 I/O22 B9 (io), 31 I/O23 B8 (io), 32 TMS (in), 33 CLK1/IN1 (in), 34 GND (power), 35 TDO (out), 36 I/O24 B0 (io), 37 I/O25 B1 (io), 38 I/O26 B2 (io), 39 I/O27 B3 (io), 40 I/O28 B4 (io), 41 I/O29 B5 (io), 42 I/O30 B6 (io), 43 I/O31 B7 (io), 44 VCC (power)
